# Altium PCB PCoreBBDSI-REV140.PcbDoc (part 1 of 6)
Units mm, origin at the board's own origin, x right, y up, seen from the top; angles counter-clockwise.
Board outline 100 x 72 mm, 6 copper layers (Top Layer, Int1 (GND), Int2 (Sign), Int3 (Sign), Int4 (GND), Bottom Layer), stack 1.551 mm thick; 358 components, 403 nets, 1535 pads, 844 vias.
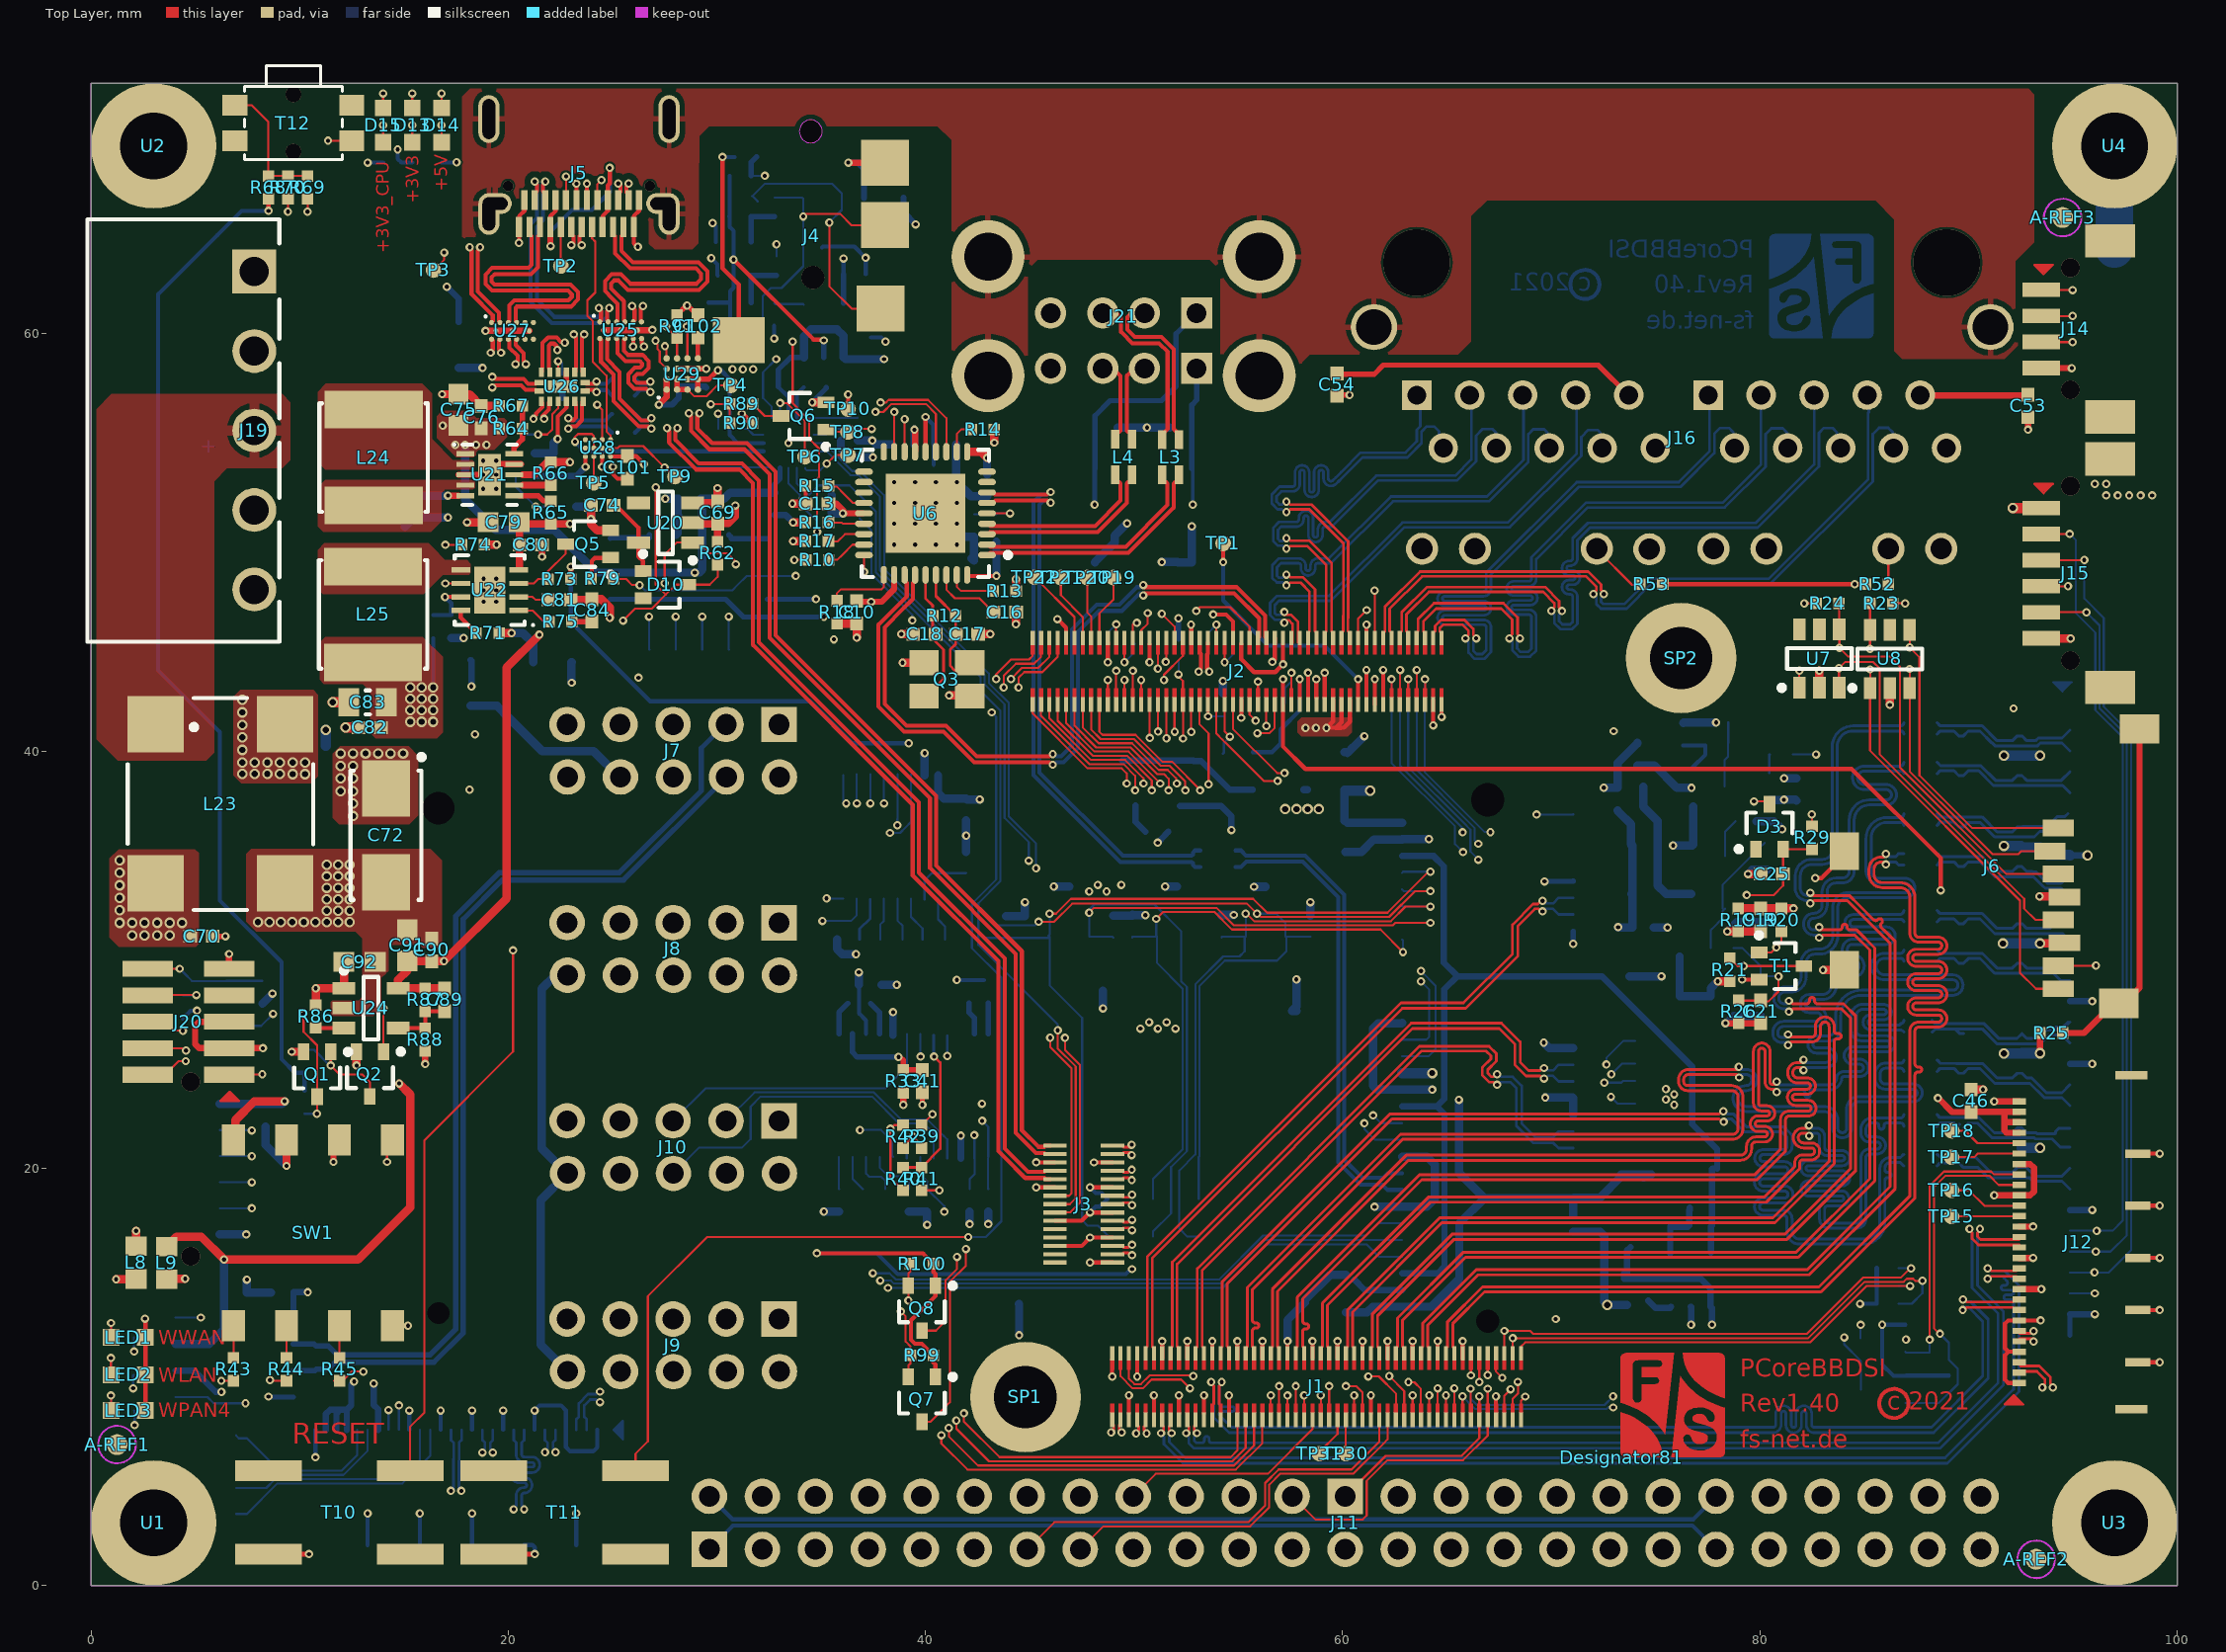
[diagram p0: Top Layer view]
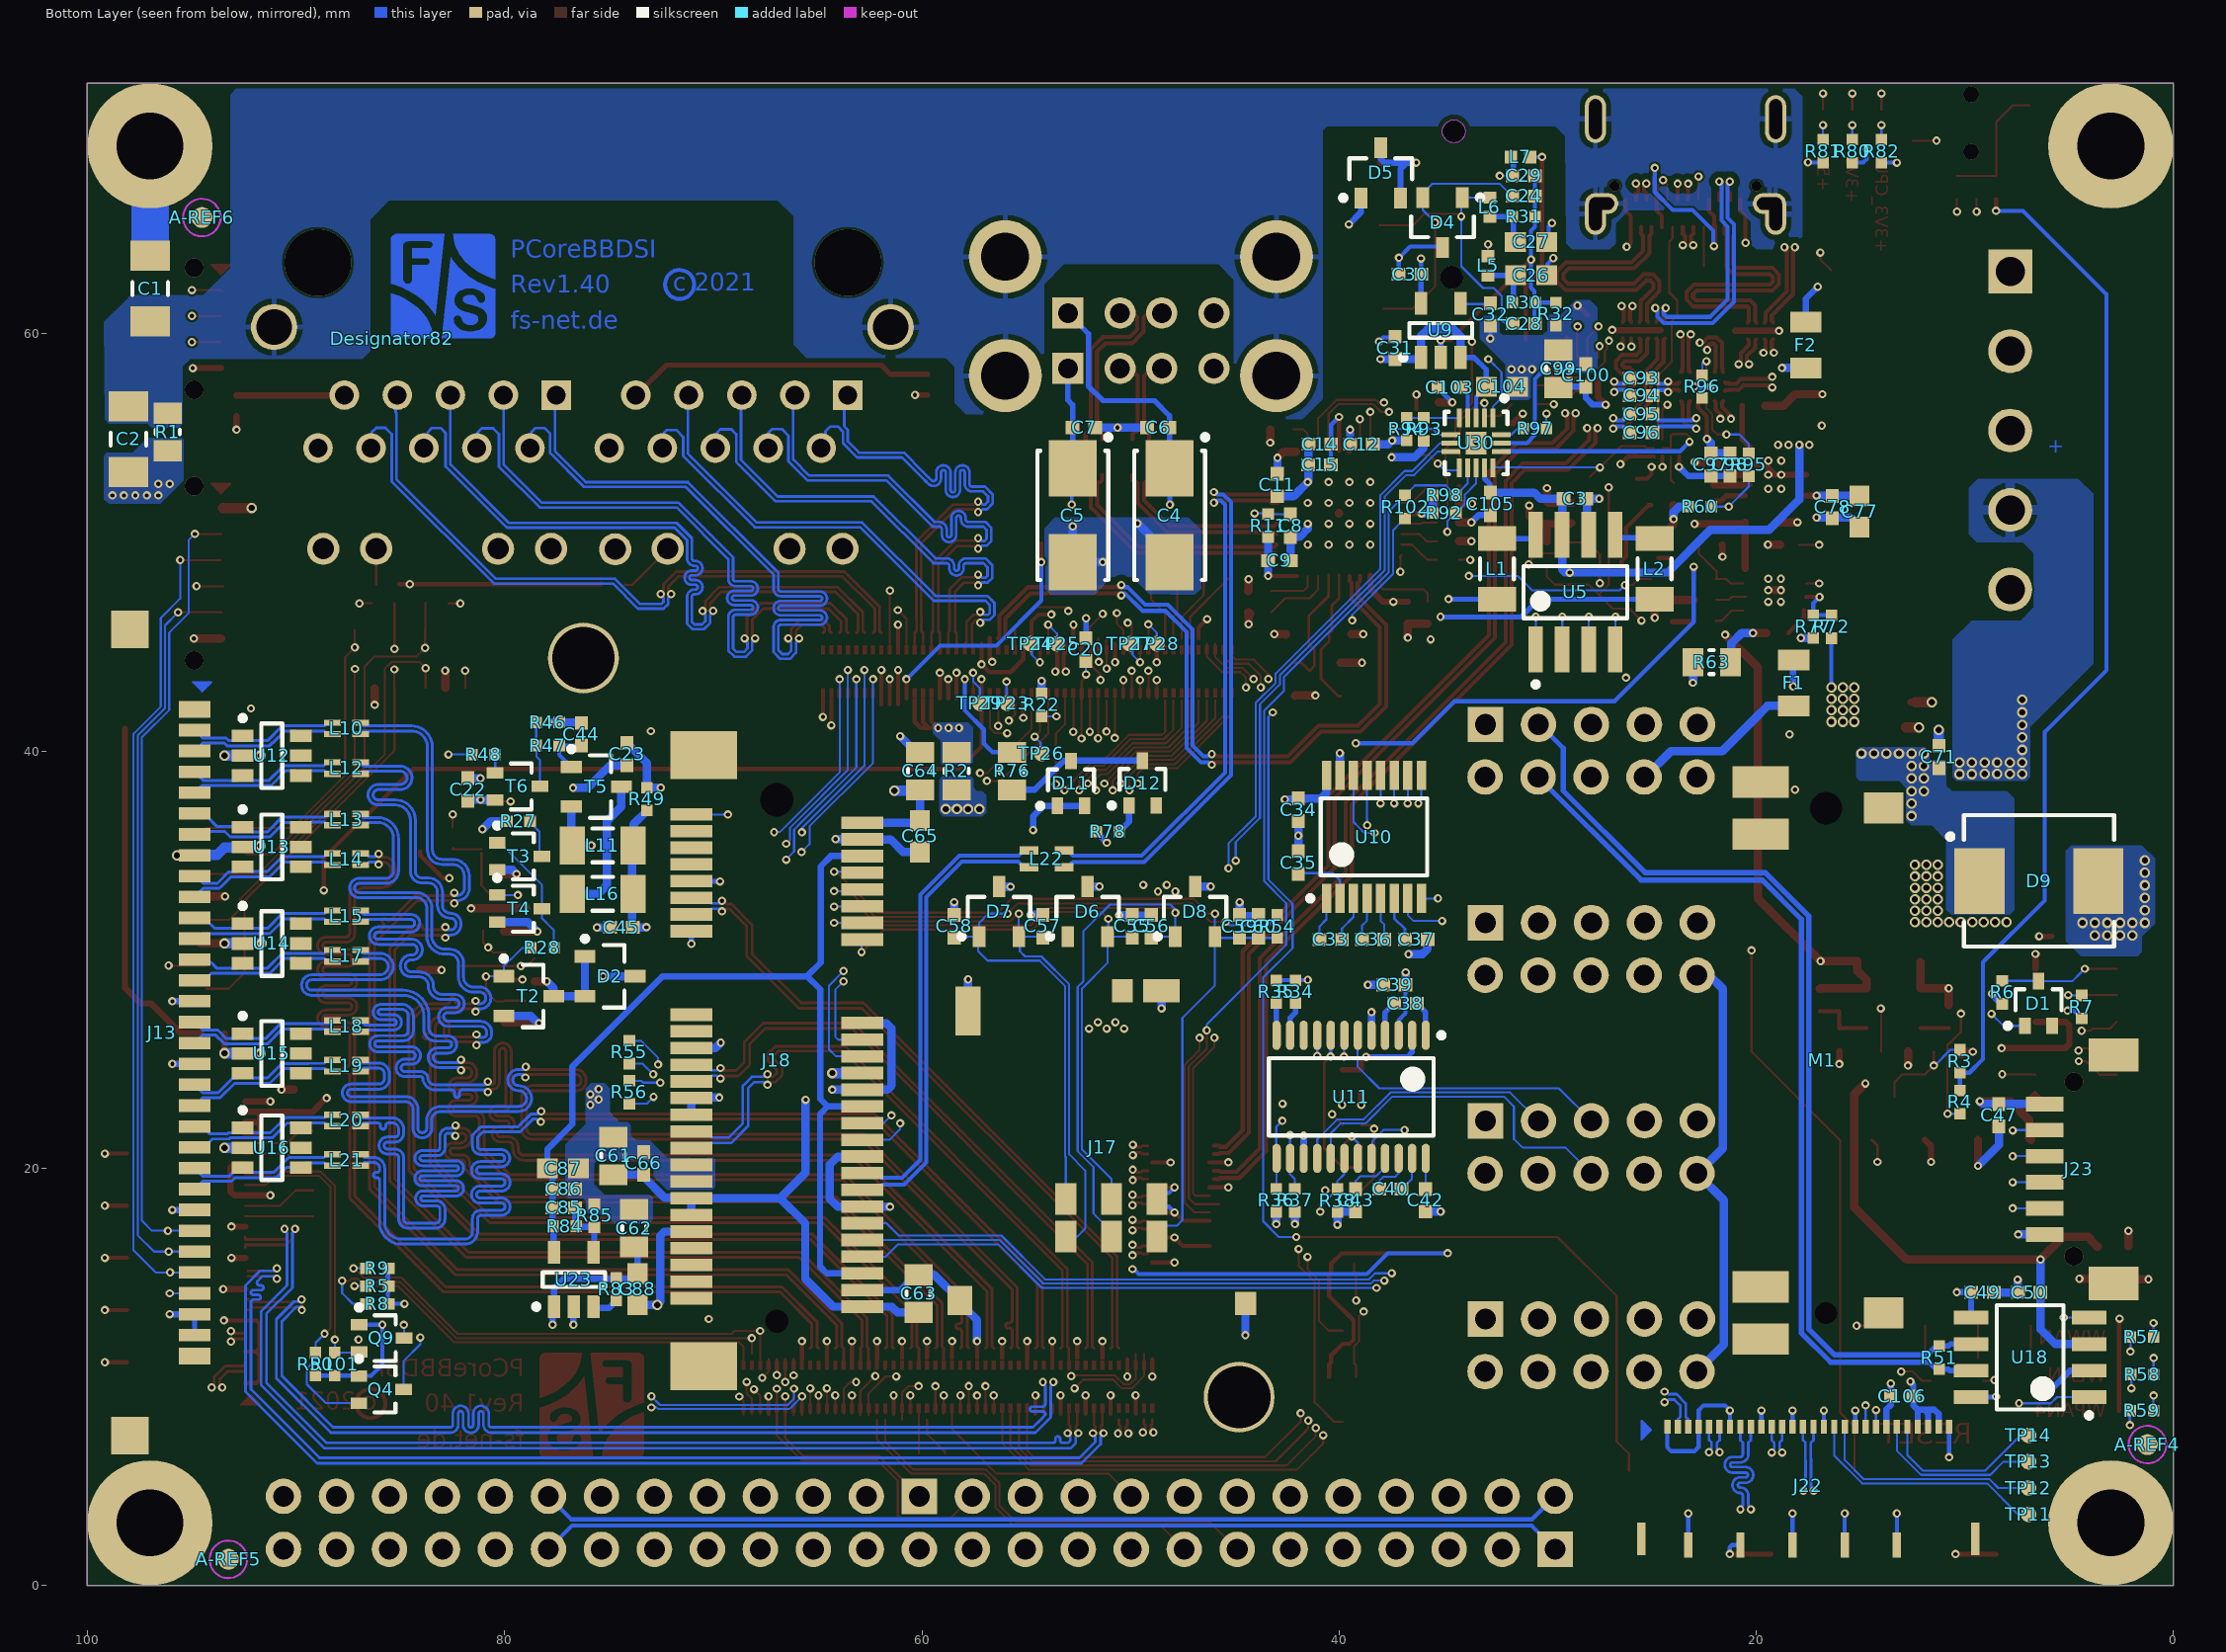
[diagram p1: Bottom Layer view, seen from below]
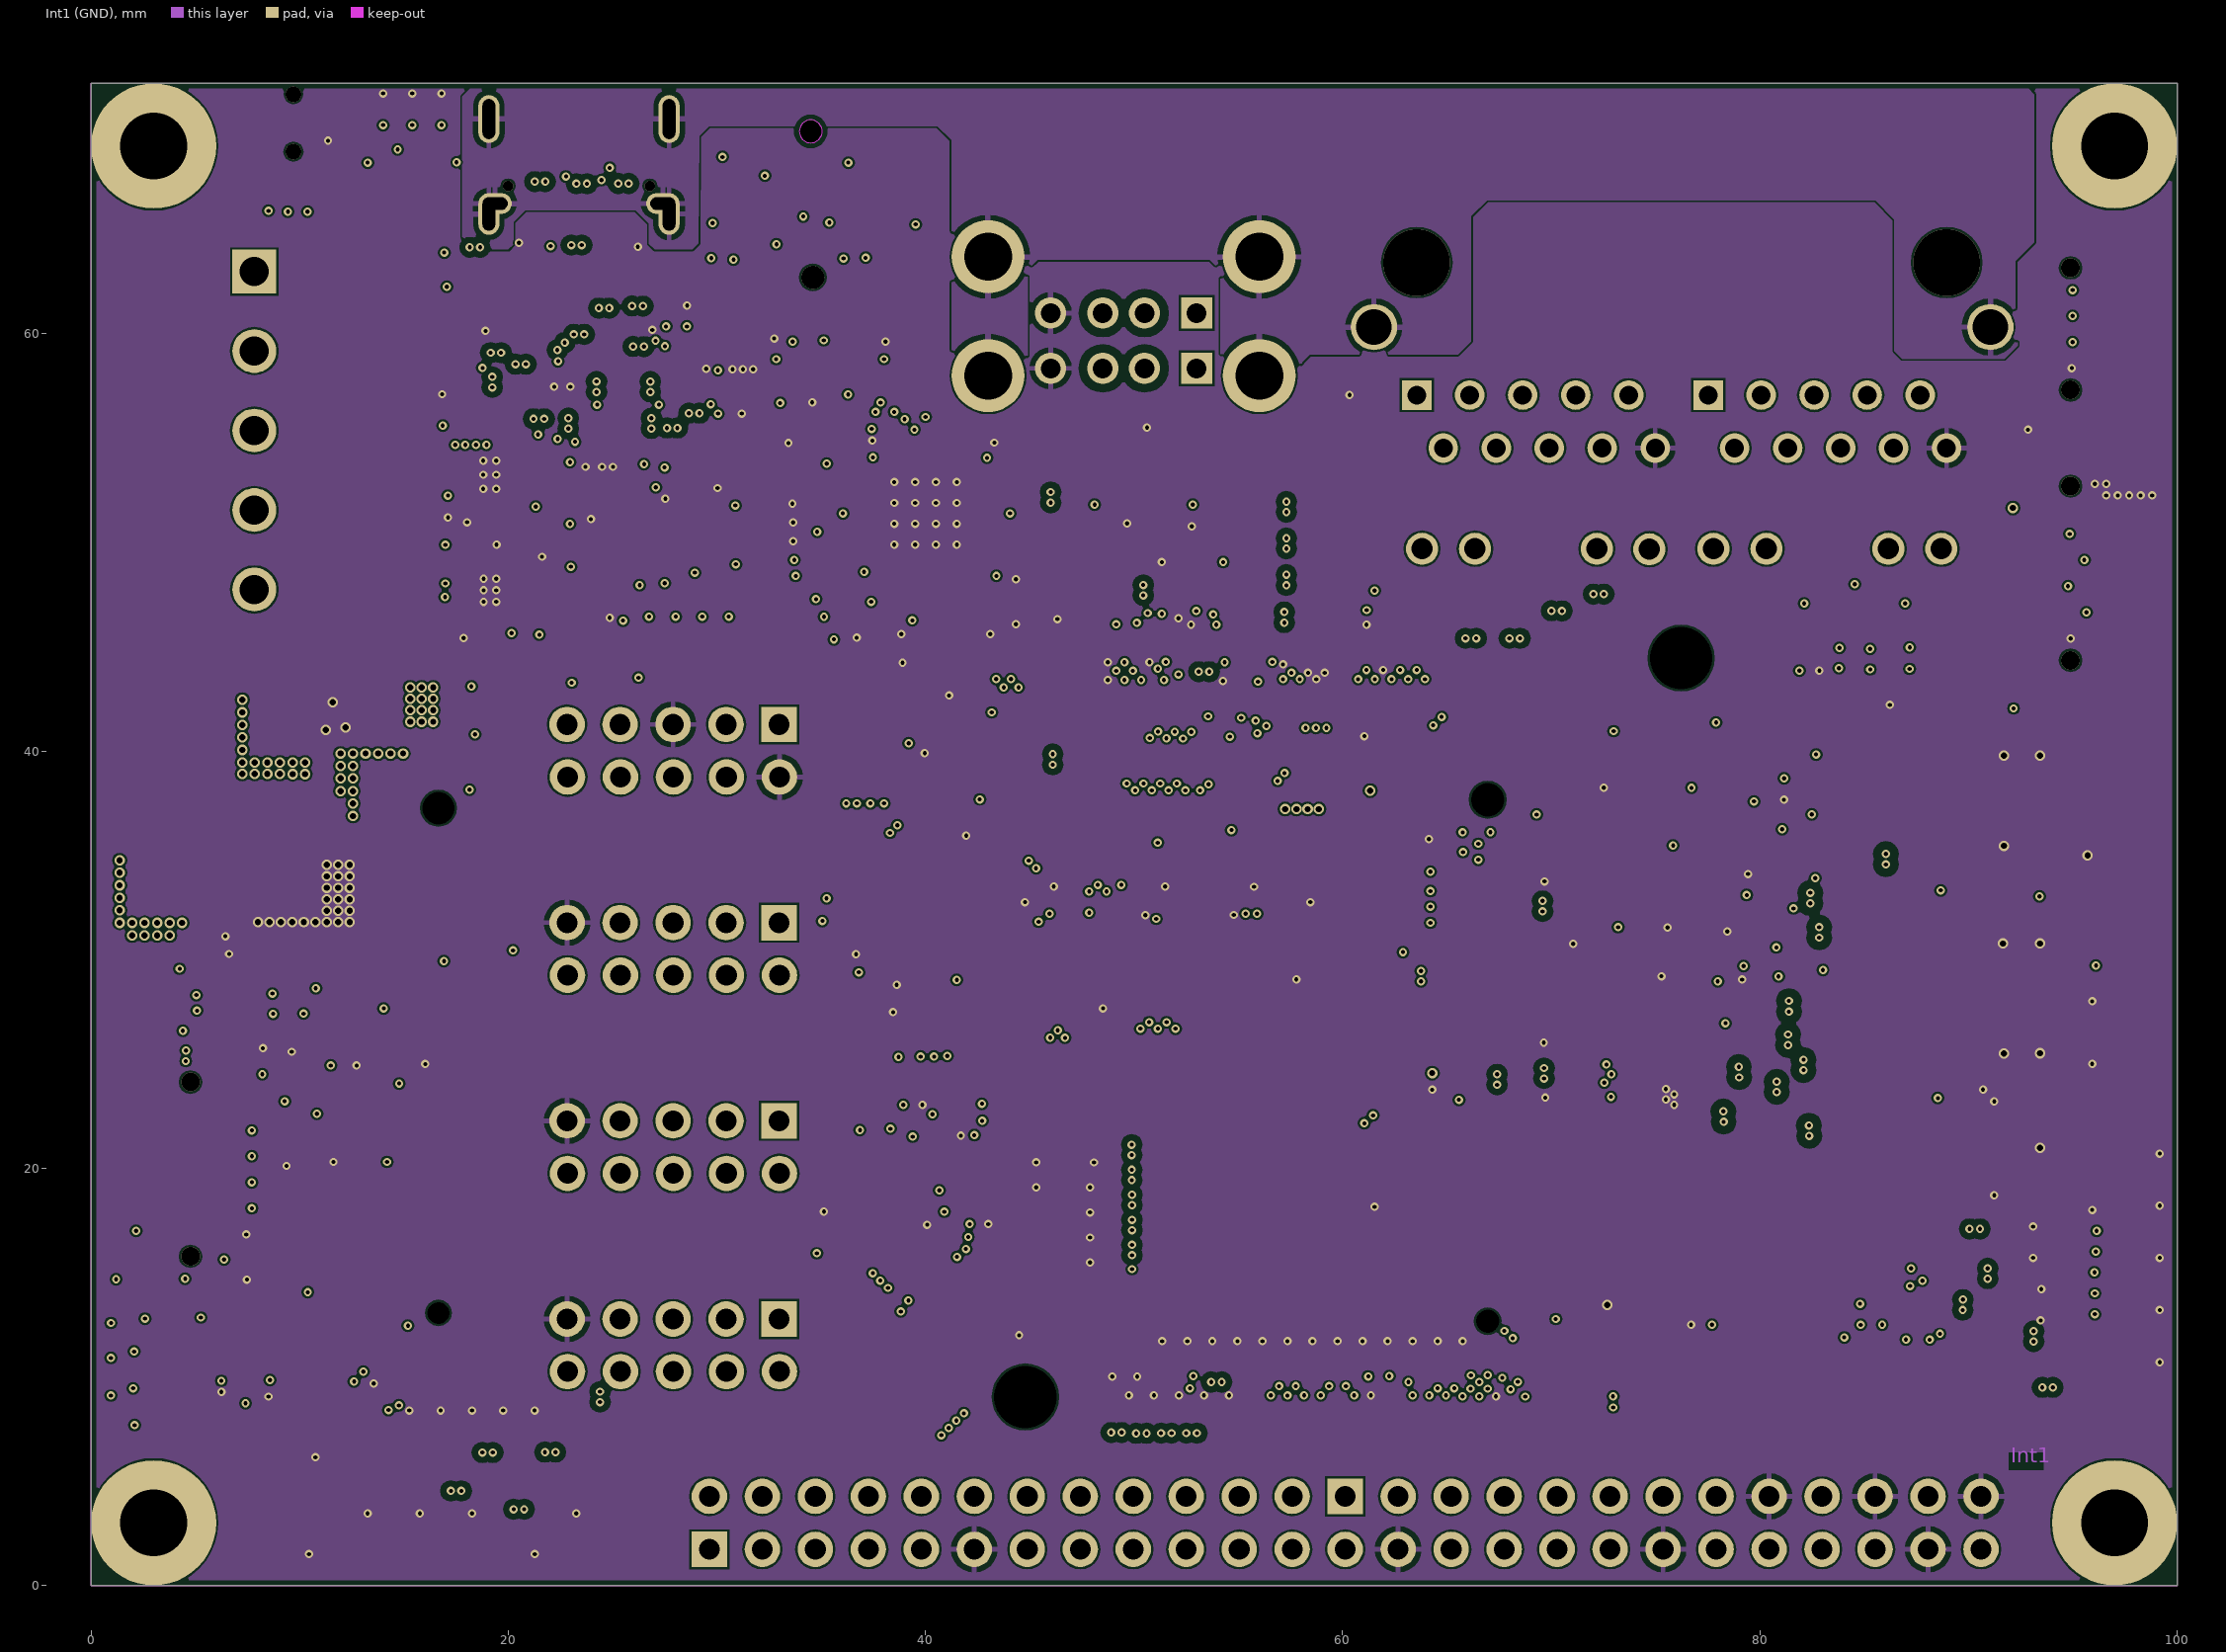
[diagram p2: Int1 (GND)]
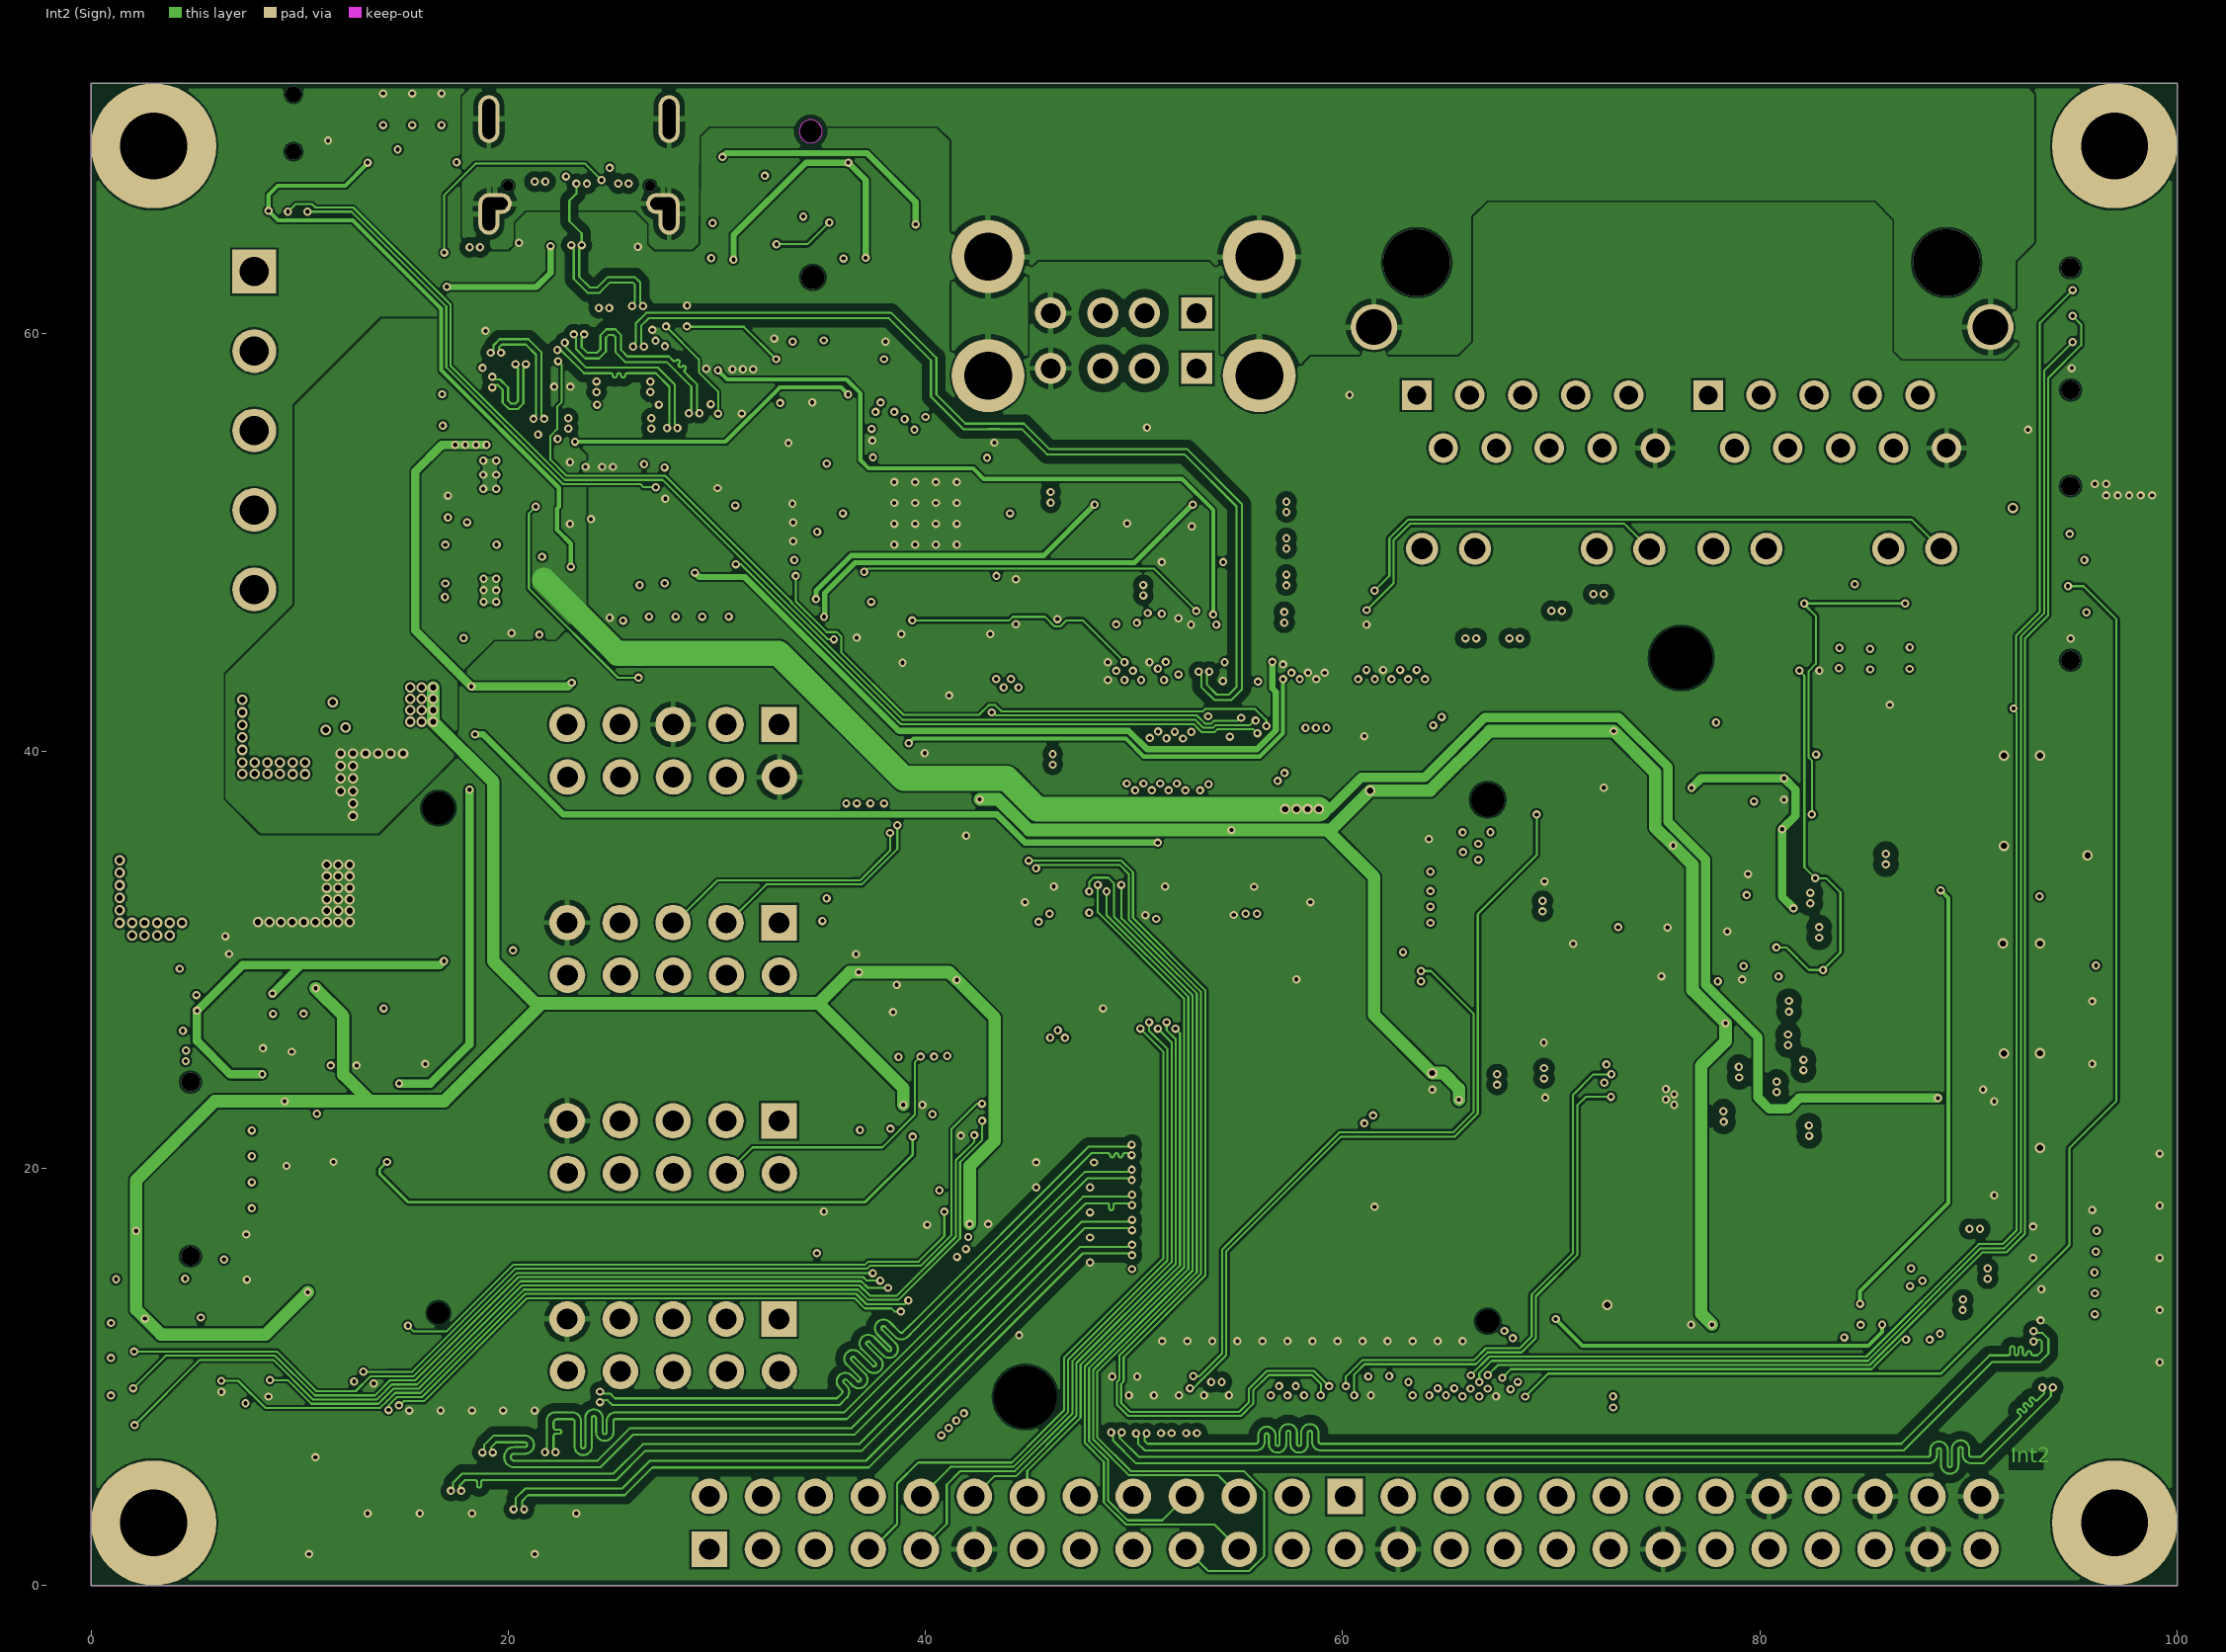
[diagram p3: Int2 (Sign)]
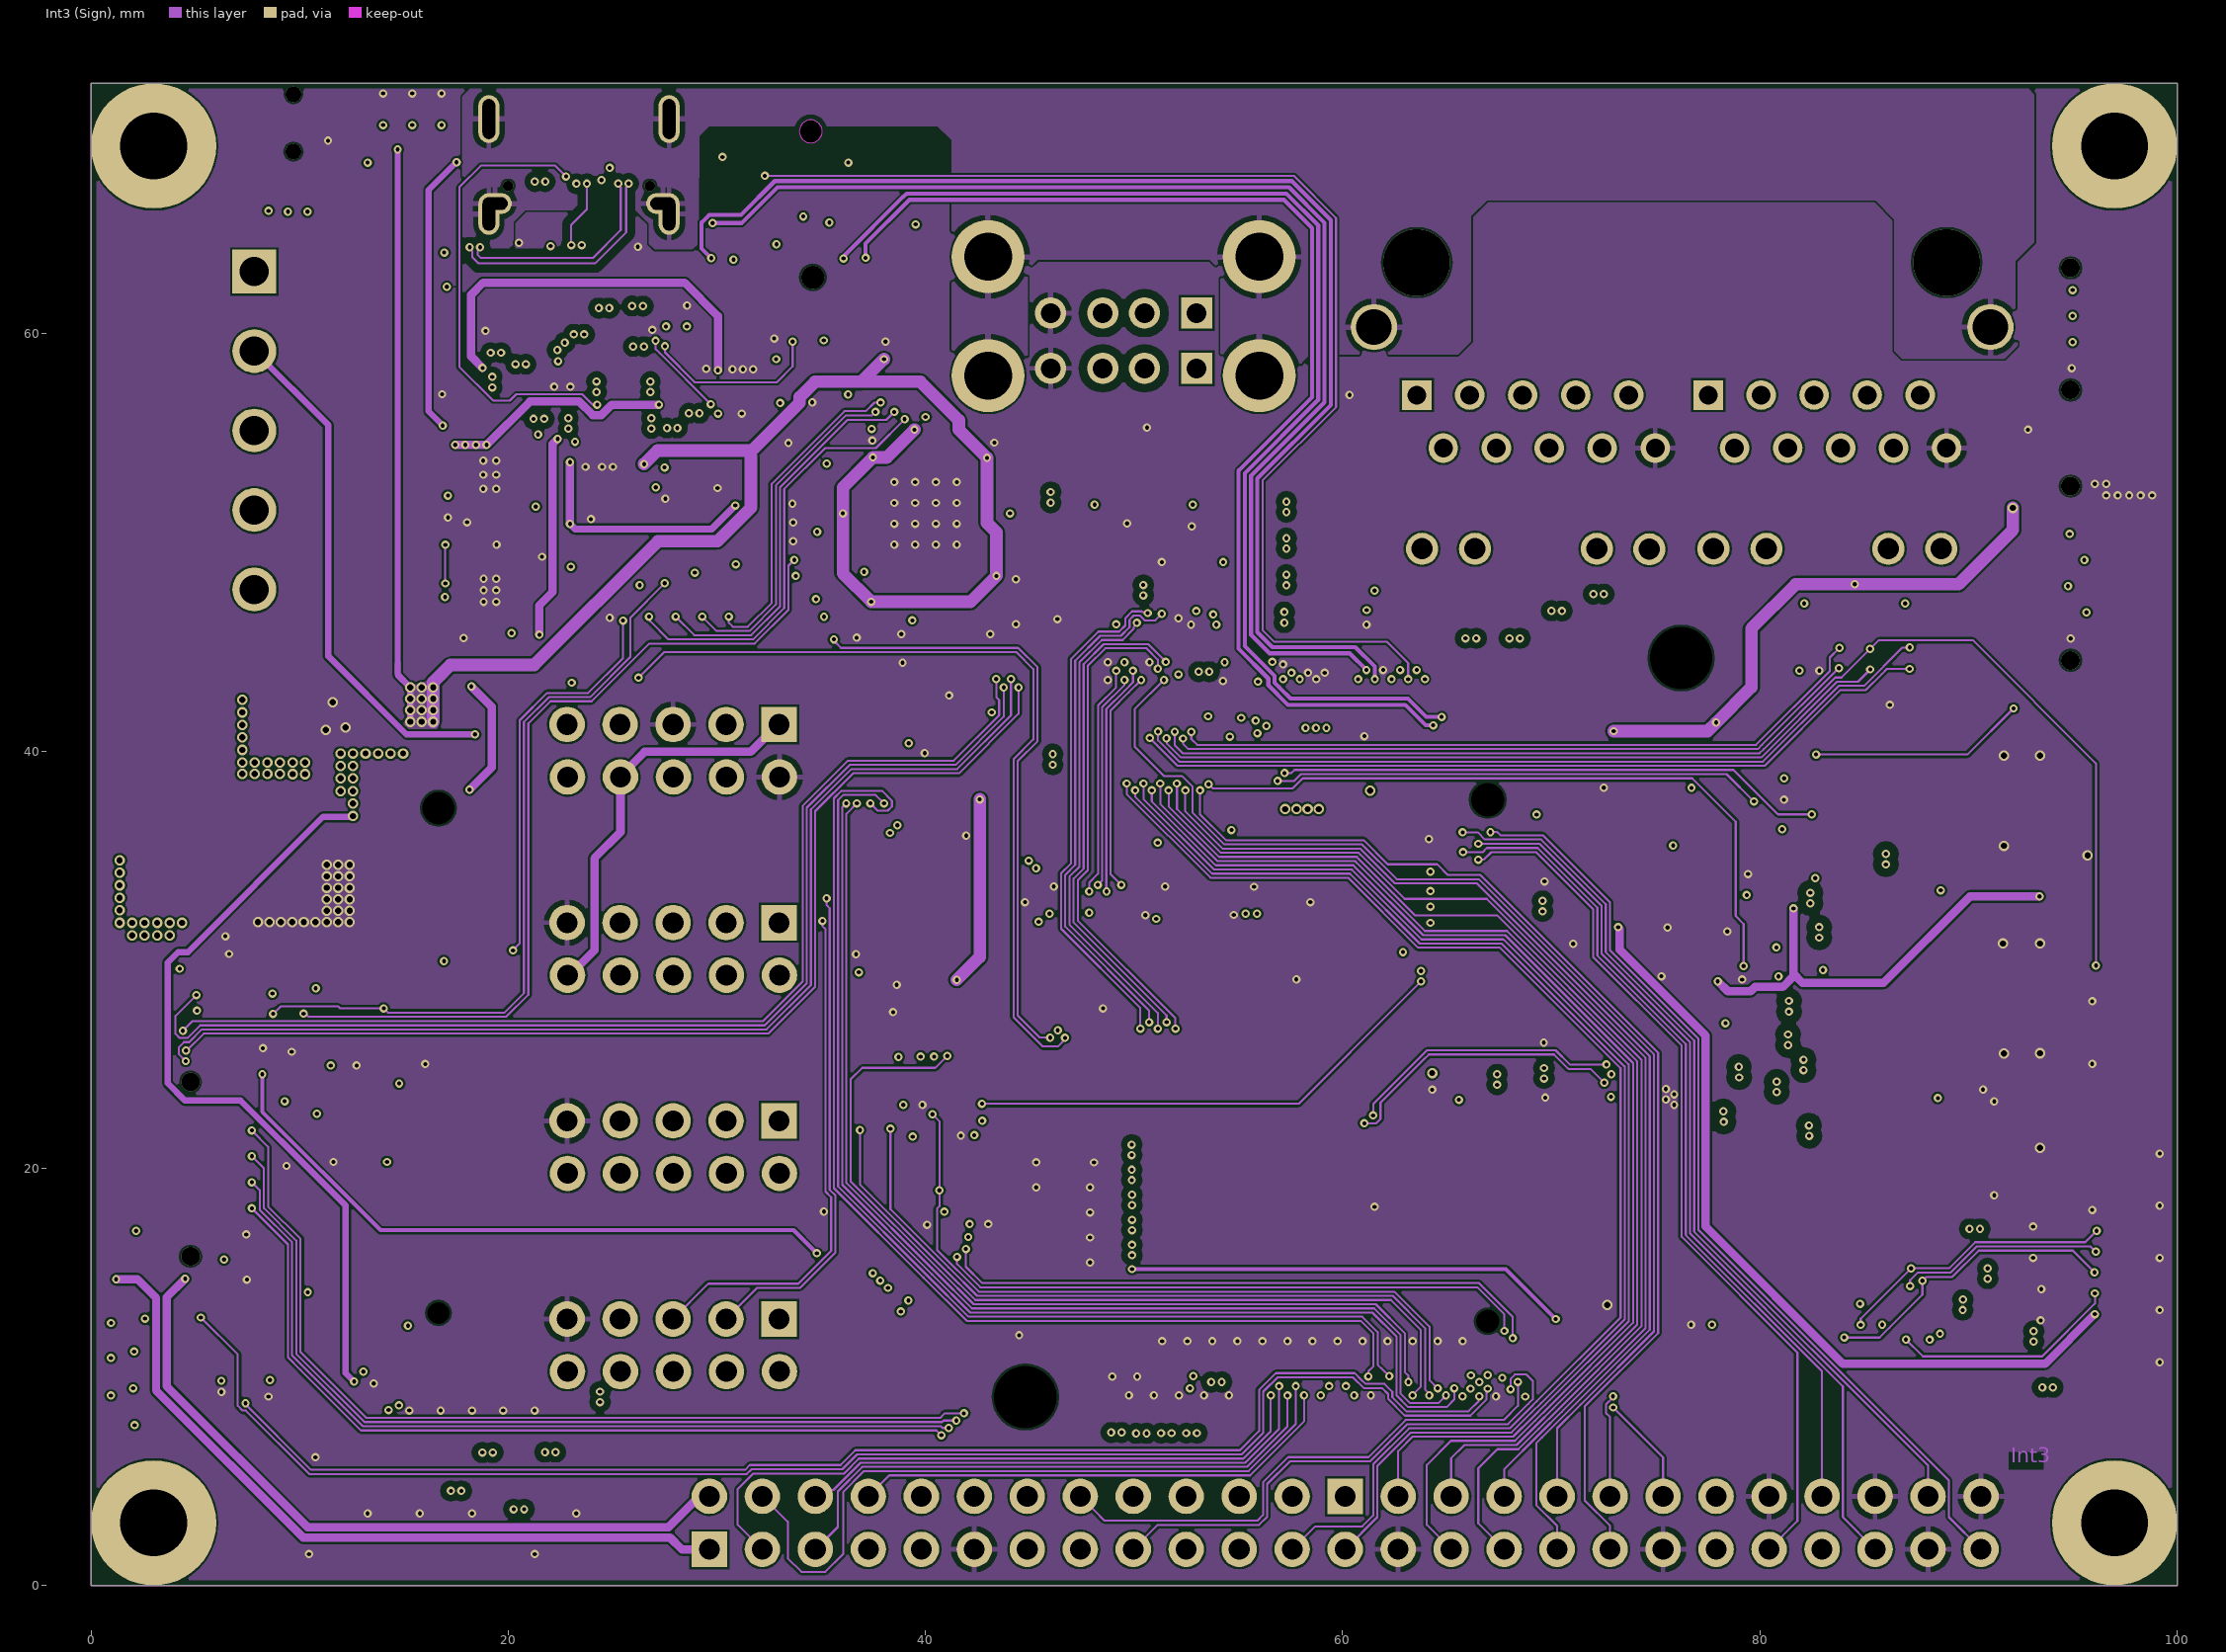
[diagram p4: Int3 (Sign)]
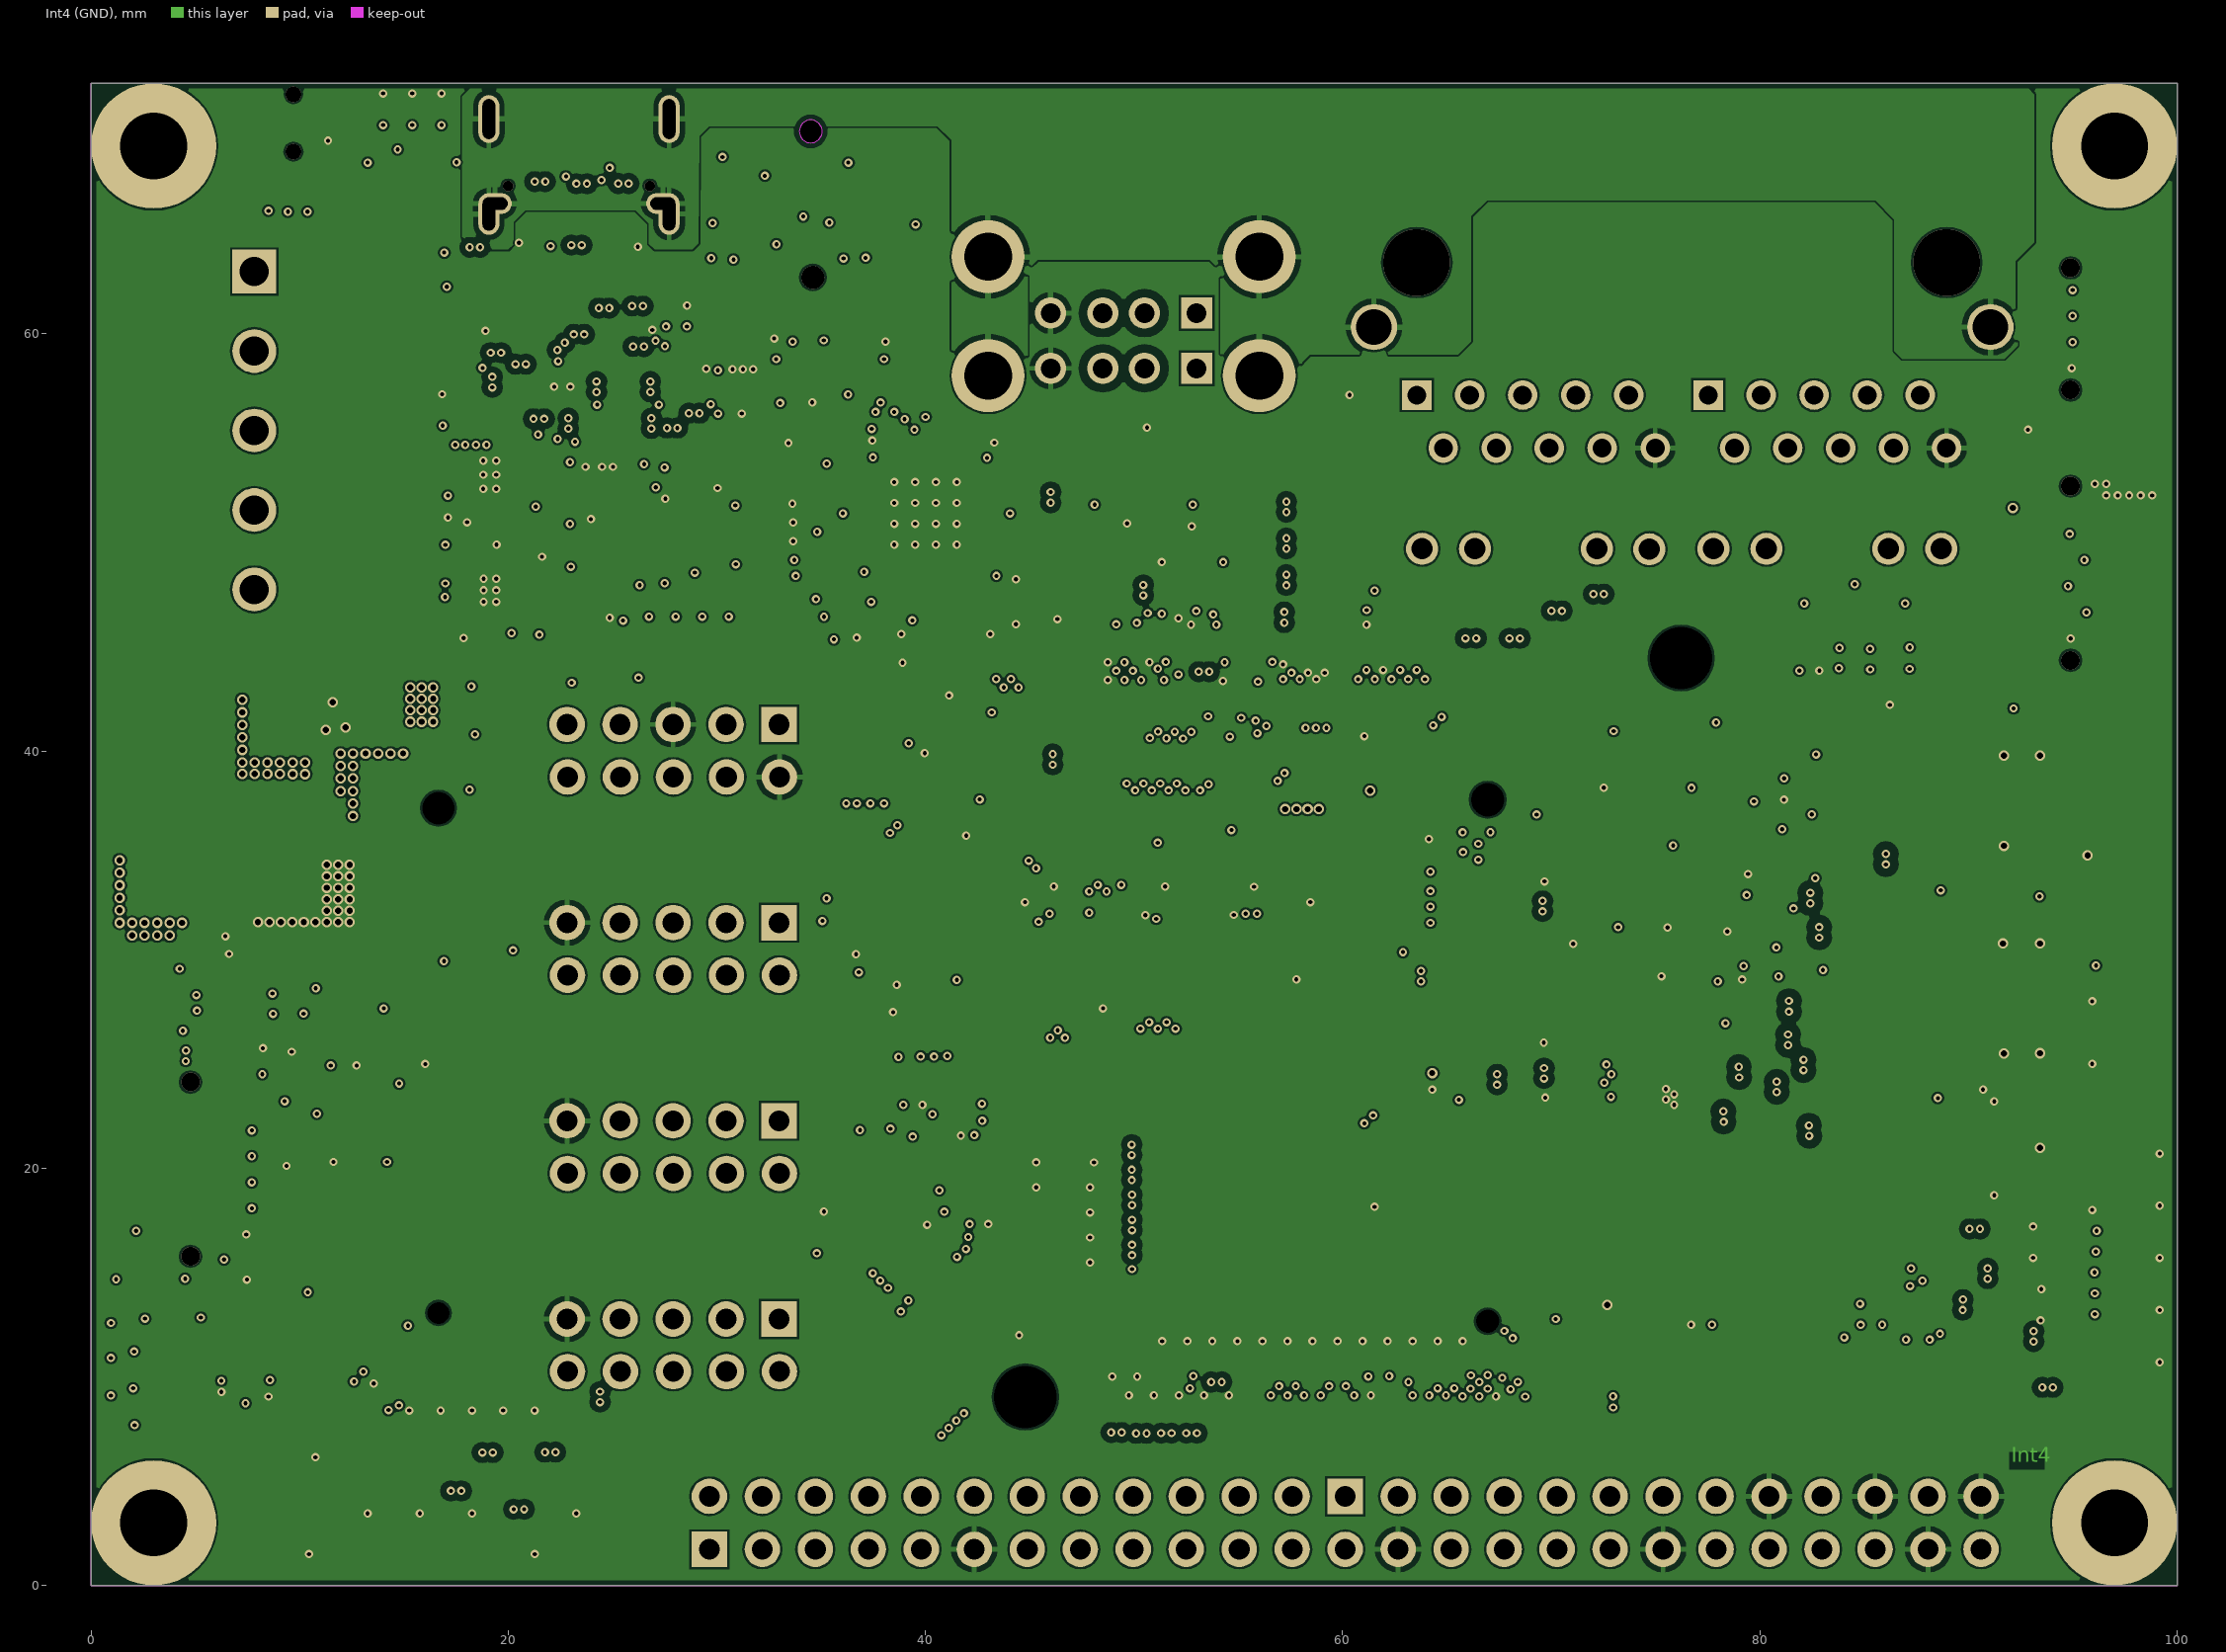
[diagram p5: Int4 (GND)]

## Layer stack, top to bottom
Top Solder: solder mask 0.0102, SM-001, Dk 3.5
Top Layer: signal copper 0.035
Dielectric 1: prepreg 0.0711, PP-006, Dk 4.1
Dielectric 2: prepreg 0.0711, PP-006, Dk 4.1
Int1 (GND): signal copper 0.035
Dielectric 3: core 0.4572, Core-035, Dk 4.7
Int2 (Sign): signal copper 0.035
Dielectric 4: prepreg 0.0711, PP-006, Dk 4.1
Dielectric 5: prepreg 0.0711, PP-006, Dk 4.1
Int3 (Sign): signal copper 0.035
Dielectric 6: core 0.4572, Core-035, Dk 4.7
Int4 (GND): signal copper 0.035
Dielectric 7: prepreg 0.0711, PP-006, Dk 4.1
Dielectric 8: prepreg 0.0711, PP-006, Dk 4.1
Bottom Layer: signal copper 0.035
Bottom Solder: solder mask 0.0102, SM-001, Dk 3.5

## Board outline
0,72 0,0 100,0 100,72
cut-out: 34.5,69.15 ccw(c34.5,69.7) 35.05,69.7 ccw(c34.5,69.7) 34.5,70.25 ccw(c34.5,69.7) 33.95,69.7 ccw(c34.5,69.7)

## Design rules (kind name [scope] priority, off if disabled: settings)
BoardOutlineClearance mdCopperDimension [All] p1: gap=0.254 ignorepadtopadclearanceinfootprint=FALSE except(0: Arc-SplitContinuation Track-SplitContinuation SMDPad-SplitContinuation THPad-SplitContinuation Via-SplitContinuation Fill-SplitContinuation Poly-SplitContinuation Region-SplitContinuation Text-SplitContinuation)
Clearance Clearance_ETH [InDifferentialPairClass('ETHERNET') and not InAnyComponent vs InNet('GND')] p1: gap=0.4 ignorepadtopadclearanceinfootprint=FALSE except(0.2: SMDPad-SMDPad SMDPad-THPad SMDPad-Via SMDPad-Fill SMDPad-Poly SMDPad-Region SMDPad-Text SMDPad-Hole Via-Via Via-Fill Via-Poly Via-Region Via-Text Via-Hole)
Clearance Clearance_USB [InDifferentialPairClass('USB') vs (InNet('GND') or InNet('GND_SHIELD')) and not InAnyComponent] p2: gap=0.4 ignorepadtopadclearanceinfootprint=FALSE except(0.2: SMDPad-SMDPad SMDPad-THPad SMDPad-Via SMDPad-Fill SMDPad-Poly SMDPad-Region SMDPad-Text SMDPad-Hole Via-Via Via-Fill Via-Poly Via-Region Via-Text Via-Hole)
Clearance Clearance_DSI [(InDifferentialPairClass('MIPI-DSI') or InDifferentialPairClass('MIPI-DSI_A'))and not InAnyComponent vs InNet('GND')] p3: gap=0.4 ignorepadtopadclearanceinfootprint=FALSE except(0.2: SMDPad-SMDPad SMDPad-THPad SMDPad-Via SMDPad-Fill SMDPad-Poly SMDPad-Region SMDPad-Text SMDPad-Hole)
Clearance Clearance_CSI [(InDifferentialPairClass('MIPI-CSI_A') or InDifferentialPairClass('MIPI-CSI_B')) and not InAnyComponent vs InNet('GND')] p4: gap=0.4 ignorepadtopadclearanceinfootprint=FALSE except(0.2: SMDPad-SMDPad SMDPad-THPad SMDPad-Via SMDPad-Fill SMDPad-Poly SMDPad-Region SMDPad-Text SMDPad-Hole Via-Via Via-Fill Via-Poly Via-Region Via-Text Via-Hole)
Clearance Clearance_MPCIE [InDifferentialPairClass('mPCIe') and not InAnyComponent vs InNet('GND')] p5: gap=0.4 ignorepadtopadclearanceinfootprint=FALSE except(0.2: SMDPad-SMDPad SMDPad-THPad SMDPad-Via SMDPad-Fill SMDPad-Poly SMDPad-Region SMDPad-Text SMDPad-Hole Via-Via Via-Fill Via-Poly Via-Region Via-Text Via-Hole)
Clearance [All] p6: gap=0.1 ignorepadtopadclearanceinfootprint=FALSE
DiffPairsRouting DiffPairsRouting_MIPI-CSIA [InDifferentialPairClass('MIPI-CSI_A')] p1: maxlimit=0.254 minlimit=0.134 mostfreqgap=0.217 toplayer_maxgap=0.134 toplayer_prefgap=0.134 toplayer_minwidth=0.127 toplayer_maxwidth=0.127 toplayer_prefwidth=0.127 midlayer2_mingap=0.217 midlayer2_maxgap=0.217 midlayer2_minwidth=0.1 midlayer2_maxwidth=0.1 midlayer2_prefwidth=0.1 midlayer13_mingap=0.217 midlayer13_maxgap=0.217 midlayer13_minwidth=0.1 midlayer13_maxwidth=0.1 midlayer13_prefwidth=0.1 bottomlayer_maxgap=0.134 bottomlayer_prefgap=0.134 bottomlayer_minwidth=0.127 bottomlayer_maxwidth=0.127 bottomlayer_prefwidth=0.127 impedanceprofiledriven=TRUE impedanceprofileid={61890842-8ADA-4508-8F82-990CEACFB491} impedanceprofilevalue=100.000000 maxuncoupledlength=12.7
DiffPairsRouting DiffPairsRouting_MIPI-CSIB [InDifferentialPairClass('MIPI-CSI_B')] p2: maxlimit=0.254 minlimit=0.134 mostfreqgap=0.217 toplayer_maxgap=0.134 toplayer_prefgap=0.134 toplayer_minwidth=0.127 toplayer_maxwidth=0.127 toplayer_prefwidth=0.127 midlayer2_mingap=0.217 midlayer2_maxgap=0.217 midlayer2_minwidth=0.1 midlayer2_maxwidth=0.1 midlayer2_prefwidth=0.1 midlayer13_mingap=0.217 midlayer13_maxgap=0.217 midlayer13_minwidth=0.1 midlayer13_maxwidth=0.1 midlayer13_prefwidth=0.1 bottomlayer_maxgap=0.134 bottomlayer_prefgap=0.134 bottomlayer_minwidth=0.127 bottomlayer_maxwidth=0.127 bottomlayer_prefwidth=0.127 impedanceprofiledriven=TRUE impedanceprofileid={61890842-8ADA-4508-8F82-990CEACFB491} impedanceprofilevalue=100.000000 maxuncoupledlength=12.7
DiffPairsRouting DiffPairsRouting_mPCIe [InDifferentialPairClass('mPCIe')] p3: maxlimit=0.254 minlimit=0.101 mostfreqgap=0.254 toplayer_maxgap=0.101 toplayer_prefgap=0.101 toplayer_minwidth=0.127 toplayer_maxwidth=0.127 toplayer_prefwidth=0.127 bottomlayer_maxgap=0.101 bottomlayer_prefgap=0.101 bottomlayer_minwidth=0.127 bottomlayer_maxwidth=0.127 bottomlayer_prefwidth=0.127 impedanceprofiledriven=TRUE impedanceprofileid={8104632F-C234-49EF-8071-15C0523083AF} impedanceprofilevalue=100.000000 maxuncoupledlength=12.7
DiffPairsRouting DiffPairsRouting_USB [InDifferentialPairClass('USB')] p4: maxlimit=0.254 minlimit=0.1 mostfreqgap=0.162 toplayer_maxgap=0.1 toplayer_prefgap=0.1 toplayer_minwidth=0.193 toplayer_maxwidth=0.193 toplayer_prefwidth=0.193 midlayer2_mingap=0.162 midlayer2_maxgap=0.162 midlayer2_minwidth=0.1 midlayer2_maxwidth=0.1 midlayer2_prefwidth=0.1 midlayer13_mingap=0.162 midlayer13_maxgap=0.162 midlayer13_minwidth=0.1 midlayer13_maxwidth=0.1 midlayer13_prefwidth=0.1 bottomlayer_maxgap=0.1 bottomlayer_prefgap=0.1 bottomlayer_minwidth=0.193 bottomlayer_maxwidth=0.193 bottomlayer_prefwidth=0.193 impedanceprofiledriven=TRUE impedanceprofileid={9E9B064C-F429-49DC-B595-341FB236020C} impedanceprofilevalue=90.000000 maxuncoupledlength=12.7
DiffPairsRouting DiffPairsRouting_ETH [InDifferentialPairClass('ETHERNET')] p5: maxlimit=0.254 minlimit=0.101 mostfreqgap=0.254 toplayer_maxgap=0.101 toplayer_prefgap=0.101 toplayer_minwidth=0.127 toplayer_maxwidth=0.127 toplayer_prefwidth=0.127 bottomlayer_maxgap=0.101 bottomlayer_prefgap=0.101 bottomlayer_minwidth=0.127 bottomlayer_maxwidth=0.127 bottomlayer_prefwidth=0.127 impedanceprofiledriven=TRUE impedanceprofileid={021EC69B-A8CB-46D2-9CD8-883BDBF6D44B} impedanceprofilevalue=100.000000 maxuncoupledlength=12.7
DiffPairsRouting DiffPairsRouting_MIPI-DSI [InDifferentialPairClass('MIPI-DSI')] p6: maxlimit=0.254 minlimit=0.1 mostfreqgap=0.254 toplayer_maxgap=0.1 toplayer_prefgap=0.1 toplayer_minwidth=0.141 toplayer_maxwidth=0.141 toplayer_prefwidth=0.141 bottomlayer_maxgap=0.1 bottomlayer_prefgap=0.1 bottomlayer_minwidth=0.141 bottomlayer_maxwidth=0.141 bottomlayer_prefwidth=0.141 impedanceprofiledriven=TRUE impedanceprofileid={A166DE6F-DE0D-4349-AD25-390A66383BFA} impedanceprofilevalue=100.000000 maxuncoupledlength=10
DiffPairsRouting DiffPairsRouting_MIPI-DSI_A [InDifferentialPairClass('MIPI-DSI_A')] p7: maxlimit=0.254 minlimit=0.1 mostfreqgap=0.254 toplayer_maxgap=0.1 toplayer_prefgap=0.1 toplayer_minwidth=0.141 toplayer_maxwidth=0.141 toplayer_prefwidth=0.141 bottomlayer_maxgap=0.1 bottomlayer_prefgap=0.1 bottomlayer_minwidth=0.141 bottomlayer_maxwidth=0.141 bottomlayer_prefwidth=0.141 impedanceprofiledriven=TRUE impedanceprofileid={A166DE6F-DE0D-4349-AD25-390A66383BFA} impedanceprofilevalue=100.000000 maxuncoupledlength=10
HoleSize [All] p1: absolutevalues=TRUE maxlimit=2540 minlimit=0.2 maxpercent=80.000 minpercent=20.000
HoleToHoleClearance mdDrill [All] p1: gap=0.203 allowstackedmicrovias=TRUE
MatchedLengths MatchedLengths_MIPI_CSI_A [InDifferentialPairClass('MIPI-CSI_A')] p1: tolerance=0.1 checknetsindiffpair=TRUE checkdiffpairvsdiffpair=FALSE checkxsignals=FALSE checkothers=FALSE
MatchedLengths MatchedLengths_MIPI_CSI_A2 [InDifferentialPairClass('MIPI-CSI_A')] p2: tolerance=0.1 checknetsindiffpair=FALSE checkdiffpairvsdiffpair=TRUE checkxsignals=TRUE checkothers=TRUE
MatchedLengths MatchedLengths_MIPI_CSI_B [InDifferentialPairClass('MIPI-CSI_B')] p3: tolerance=0.1 checknetsindiffpair=FALSE checkdiffpairvsdiffpair=TRUE checkxsignals=TRUE checkothers=TRUE
MatchedLengths MatchedLengths_MIPI_CSI_B_1 [InDifferentialPairClass('MIPI-CSI_B')] p4: tolerance=0.1 checknetsindiffpair=FALSE checkdiffpairvsdiffpair=TRUE checkxsignals=TRUE checkothers=TRUE
MatchedLengths MatchedLengths_MIPI_DSI_A [InDifferentialPairClass('MIPI-DSI_A')] p5: tolerance=0.1 checknetsindiffpair=TRUE checkdiffpairvsdiffpair=FALSE checkxsignals=FALSE checkothers=FALSE
MatchedLengths MatchedLengths_MIPI_DSI_A_2 [InDifferentialPairClass('MIPI-DSI_A')] p6: tolerance=0.2 checknetsindiffpair=FALSE checkdiffpairvsdiffpair=TRUE checkxsignals=TRUE checkothers=TRUE
MinimumSolderMaskSliver [All] p1 off: minsoldermaskwidth=0.254
PasteMaskExpansion Expansion_SMDPaste_OFF [InPadClass('SMDPaste_OFF')] p1: expansion=0
PasteMaskExpansion mlMinCreamFrame [All] p2: expansion=0
PlaneConnect [All] p1: planeconnectstyle=Direct reliefexpansion=0.508 reliefentries=4 reliefconductorwidth=0.254 reliefairgap=0.254
PolygonConnect [All] p1: thpad.connectstyle=Relief thpad.reliefconductorwidth=0.254 thpad.reliefentries=4 thpad.polygonreliefangle="90 Angle" thpad.airgapwidth=0.254 smdpad.connectstyle=Direct smdpad.reliefconductorwidth=0.254 smdpad.reliefentries=4 smdpad.polygonreliefangle="90 Angle" smdpad.airgapwidth=0.254 via.connectstyle=Direct via.reliefconductorwidth=0.254 via.reliefentries=4 via.polygonreliefangle="90 Angle" via.airgapwidth=0.254
RoutingVias [All] p1: holewidth=0.2 width=0.4 viastyle="Through Hole" minholewidth=0.2 minwidth=0.4 maxholewidth=5 maxwidth=5
SolderMaskExpansion Expansion_SMDSolder_OFF [InPadClass('SMDSolder_OFF')] p1: expansion=0 istentingtop=FALSE
SolderMaskExpansion mlMinStopFrame [All] p2: expansion=0 istentingtop=FALSE
Width [All] p1: maxlimit=2.54 minlimit=0.1 preferedwidth=0.1
24 further rules are at their usual default settings.

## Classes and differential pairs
differential pair class MIPI-CSI_A: CSI_A_CLK CSI_A_DATA0 CSI_A_DATA1 CSI_A_DATA2 CSI_A_DATA3
differential pair class MIPI-DSI: LACLK LADATA0 LADATA1 LADATA2 LADATA3 LBCLK LBDATA0 LBDATA1 LBDATA2 LBDATA3
component class "05) USB3.0 Type-C": C93 C94 C95 C96 C97 C98 C99 C100 C101 C102 C103 C104 C105 F2 J5 Q6 R60 R89 R90 R91 R92 R93 R94 R95 R96 R97 R98 R102 U25 U26 U27 U28 U29 U30
differential pair class MIPI-CSI_B: CSI_B_CLK CSI_B_DATA0 CSI_B_DATA1 CSI_B_DATA2 CSI_B_DATA3
differential pair class USB: S_TX1 S_TX2 SS_RX1 SS_RX2 SS_TX1 SS_TX2 SSRX1 SSRX2 SSTX1 SSTX2 USB1_CN_D USB1_RX USB1_TX USB_HUB_A USB_HUB_B USB_OTG USB_OTG_D USBD USBDM1 USBDM2 USBDM3 USBDM4 USBHUB_C USBOTG
differential pair class mPCIe: MPCIE_CLK MPCIE_CRX MPCIE_CTX
differential pair class ETHERNET: ETH_A_D1 ETH_A_D2 ETH_A_D3 ETH_A_D4 ETH_B_D1 ETH_B_D2 ETH_B_D3 ETH_B_D4
differential pair class MIPI-DSI_A: DSI_A_CLK DSI_A_DATA0 DSI_A_DATA1 DSI_A_DATA2 DSI_A_DATA3 DSI_B_CLK DSI_B_DATA0 DSI_B_DATA1 DSI_B_DATA2 DSI_B_DATA3
component class "10) DCDC": C69 C70 C71 C72 C74 C75 C76 C77 C78 C79 C80 C81 C82 C83 C84 C85 C86 C87 C88 C89 C90 C91 C92 D9 D10 D11 D12 D13 D14 D15 J19 L23 L24 L25 Q5 R62 R63 R64 R65 R66 R67 R68 R69 R70 R71 R72 R73 R74 R75 R76 R77 R78 R79 R80 R81 R82 R83 R84 R85 R86 R87 R88 T10 T11 T12 U20 U21 U22 U23 U24
component class "09) mPCIe": C55 C56 C57 C58 C59 C60 C61 C62 C63 C64 C65 C66 D6 D7 D8 J17 J18 L22 LED1 LED2 LED3 M1 R54 R55 R56 R57 R58 R59
component class "08) Ethernet Can": C49 C50 C53 C54 J7 J16 R51 R52 R53 U18
component class "07) LCD CAM": C44 C45 C46 C106 J12 J13 J14 J15 J22 L10 L11 L12 L13 L14 L15 L16 L17 L18 L19 L20 L21 Q4 Q7 Q8 Q9 R46 R47 R48 R49 R50 R99 R100 R101 T5 T6 U12 U13 U14 U15 U16
component class "06) Serial GPIO": C33 C34 C35 C36 C37 C38 C39 C40 C41 C42 C43 C47 F1 J8 J9 J10 J11 J23 L8 L9 R33 R34 R35 R36 R37 R38 R39 R40 R41 R42 R43 R44 R45 SW1 U10 U11
component class "04) USB AUDIO SD": C19 C20 C21 C22 C23 C24 C25 C26 C27 C28 C29 C30 C31 C32 D2 D3 D4 D5 J4 J6 L5 L6 L7 R19 R20 R21 R22 R23 R24 R25 R26 R27 R28 R29 R30 R31 R32 T1 T2 T3 T4 U7 U8 U9
component class "03) USB-HUB": C3 C4 C5 C6 C7 C8 C9 C10 C11 C12 C13 C14 C15 C16 C17 C18 J21 L1 L2 L3 L4 Q3 R10 R11 R12 R13 R14 R15 R16 R17 R18 U5 U6
component class "02) PicoCore B2B": D1 J1 J2 J3 J20 Q1 Q2 R2 R3 R4 R5 R6 R7 R8 R9 SP1 SP2
component class "01) Title Page": A-REF1 A-REF2 A-REF3 A-REF4 A-REF5 A-REF6 C1 C2 LABEL1 PCB1 R1 U1 U2 U3 U4
polygon class PolygonThermal_ON_Width50000_Gap100000: Polygon_1_Net_GND
polygon class PolygonThermal_ON_Width39400_Gap100000: Polygon_1_Net_VIN Polygon_2_Net_+3V3 Polygon_2_Net_N$3
polygon class PolygonThermal_ON_Width78700_Gap100000: Polygon_6_Net_GND
polygon class PolygonThermal_OFF: Polygon_1_Net_+3V3 Polygon_1_Net_GNDIN Polygon_1_Net_N$3 Polygon_1_Net_N$36 Polygon_1_Net_N$65 Polygon_1_Net_N$90 Polygon_1_Net_POWERIN Polygon_2_Net_GNDIN Polygon_3_Net_GND Polygon_4_Net_GND
pad class SMDSolder_OFF: A-REF1-P$1 A-REF2-P$1 A-REF3-P$1 A-REF4-P$1 A-REF5-P$1 A-REF6-P$1
pad class SMDPaste_OFF: A-REF1-P$1 A-REF2-P$1 A-REF3-P$1 A-REF4-P$1 A-REF5-P$1 A-REF6-P$1 C1-1 C1-2 C2-1 C2-2 C3-1 C3-2 C4-1 C4-2 C5-1 C5-2 C6-1 C6-2 C7-1 C7-2 C8-1 C8-2 C9-1 C9-2 C10-1 C10-2 C11-1 C11-2 C12-1 C12-2 C13-1 C13-2 C15-1 C15-2 C16-1 C16-2 C18-1 C18-2 C19-1 C19-2 C25-1 C25-2 C27-1 C27-2 C29-1 C29-2 C30-1 C30-2 C31-1 C31-2 C32-1 C32-2 C33-1 C33-2 C34-1 C34-2 C35-1 C35-2 C36-1 C36-2 C37-1 C37-2 C40-1 C40-2 C41-1 C41-2 C42-1 C42-2 C43-1 C43-2 C44-1 C44-2 C45-1 C45-2 C46-1 C46-2 C49-1 C49-2 C53-1 C53-2 C56-1 C56-2 C57-1 C57-2 C58-1 C58-2 C59-1 C59-2 C60-1 C60-2 C61-1 C61-2 C63-1 C63-2 C64-1 C64-2 C66-1 C66-2 C70-1 C70-2 C71-1 C71-2 C72-1 C72-2 C74-1 C74-2 C75-1 C75-2 C76-1 C76-2 C77-1 C77-2 C78-1 C78-2 C79-1 C79-2 C80-1 C80-2 C81-1 C81-2 C82-1 C82-2 C85-1 C85-2 C97-1 C97-2 C101-1 C101-2 C102-1 C102-2 C104-1 C104-2 C114-1 C114-2 C116-1 C116-2 IC11-P$37 IC17-9 R2-1 R2-2 R3-1 R3-2 R4-1 R4-2 R5-1 R5-2 R8-1 R8-2 R9-1 R9-2 R11-1 R11-2 R12-1 R12-2 R13-1 R13-2 R14-1 R14-2 R15-1 R15-2 R16-1 R16-2 R17-1 R17-2 R18-1 R18-2 R20-1 R20-2 R21-1 R21-2 R24-1 R24-2 R25-1 R25-2 R26-1 R26-2 R28-1 R28-2 R32-1 R32-2 R33-1 R33-2 R34-1 R34-2 R35-1 R35-2 R36-1 R36-2 R41-1 R41-2 R42-1 R42-2 R43-1 R43-2 R44-1 R44-2 R45-1 R45-2 R47-1 R47-2 R48-1 R48-2 R49-1 R49-2 R50-1 R50-2 R51-1 R51-2 R52-1 R52-2 R53-1 R53-2 R54-1 R54-2 R55-1 R55-2 R56-1 R56-2 R57-1 R57-2 R58-1 R58-2 R62-1 R62-2 R63-1 R63-2 R64-1 R64-2 R65-1 R65-2 R66-1 R66-2 R67-1 R67-2 R69-1 R69-2 R70-1 R70-2 R72-1 R72-2 R75-1 R75-2 R76-1 R76-2 R77-1 R77-2 R78-1 R78-2 R79-1 R79-2 R80-1 R80-2 R81-1 R81-2 R86-1 R86-2 U$11-11
differential pair CSI_A_DATA3: +CSI_A_DATA3_P -CSI_A_DATA3_N
differential pair CSI_A_DATA2: +CSI_A_DATA2_P -CSI_A_DATA2_N
differential pair CSI_A_DATA1: +CSI_A_DATA1_P -CSI_A_DATA1_N
differential pair CSI_A_DATA0: +CSI_A_DATA0_P -CSI_A_DATA0_N
differential pair CSI_A_CLK: +CSI_A_CLK_P -CSI_A_CLK_N
differential pair CSI_B_DATA3: +CSI_B_DATA3_P -CSI_B_DATA3_N
differential pair CSI_B_DATA2: +CSI_B_DATA2_P -CSI_B_DATA2_N
differential pair USB_OTG_D: +USB_OTG_D_P -USB_OTG_D_N
differential pair CSI_B_DATA1: +CSI_B_DATA1_P -CSI_B_DATA1_N
differential pair CSI_B_DATA0: +CSI_B_DATA0_P -CSI_B_DATA0_N
differential pair CSI_B_CLK: +CSI_B_CLK_P -CSI_B_CLK_N
differential pair USB1_CN_D: +USB1_CN_D_P -USB1_CN_D_N
differential pair USB1_TX: +USB1_TX_P -USB1_TX_N
differential pair USB1_RX: +USB1_RX_P -USB1_RX_N
differential pair SSTX2: +SSTX2_P -SSTX2_N
differential pair SSTX1: +SSTX1_P -SSTX1_N
differential pair SSRX2: +SSRX2_P -SSRX2_N
differential pair SSRX1: +SSRX1_P -SSRX1_N
differential pair SS_TX2: +SS_TX2_P -SS_TX2_N
differential pair SS_TX1: +SS_TX1_P -SS_TX1_N
differential pair SS_RX2: +SS_RX2_P -SS_RX2_N
differential pair SS_RX1: +SS_RX1_P -SS_RX1_N
differential pair S_TX2: +S_TX2_P -S_TX2_N
differential pair S_TX1: +S_TX1_P -S_TX1_N
differential pair LBDATA3: +LBDATA3_P -LBDATA3_N
differential pair LBDATA2: +LBDATA2_P -LBDATA2_N
differential pair LBDATA1: +LBDATA1_P -LBDATA1_N
differential pair LBDATA0: +LBDATA0_P -LBDATA0_N
differential pair LBCLK: +LBCLK_P -LBCLK_N
differential pair LADATA3: +LADATA3_P -LADATA3_N
differential pair LADATA2: +LADATA2_P -LADATA2_N
differential pair LADATA1: +LADATA1_P -LADATA1_N
differential pair LADATA0: +LADATA0_P -LADATA0_N
differential pair LACLK: +LACLK_P -LACLK_N
differential pair USBD: +USBD_P -USBD_N
differential pair USBHUB_C: +USBHUB_C_P -USBHUB_C_N
differential pair USBDM4: +USBDM4_P -USBDM4_N
differential pair USBDM3: +USBDM3_P -USBDM3_N
differential pair USBDM2: +USBDM2_P -USBDM2_N
differential pair USBDM1: +USBDM1_P -USBDM1_N
differential pair USB_HUB_B: +USB_HUB_B_P -USB_HUB_B_N
differential pair USB_HUB_A: +USB_HUB_A_P -USB_HUB_A_N
differential pair MPCIE_CTX: +MPCIE_CTX_P -MPCIE_CTX_N
differential pair MPCIE_CRX: +MPCIE_CRX_P -MPCIE_CRX_N
differential pair MPCIE_CLK: +MPCIE_CLK_P -MPCIE_CLK_N
differential pair ETH_B_D4: +ETH_B_D4_P -ETH_B_D4_N
differential pair ETH_B_D3: +ETH_B_D3_P -ETH_B_D3_N
differential pair ETH_B_D2: +ETH_B_D2_P -ETH_B_D2_N
differential pair ETH_B_D1: +ETH_B_D1_P -ETH_B_D1_N
differential pair ETH_A_D4: +ETH_A_D4_P -ETH_A_D4_N
differential pair ETH_A_D3: +ETH_A_D3_P -ETH_A_D3_N
differential pair ETH_A_D2: +ETH_A_D2_P -ETH_A_D2_N
differential pair ETH_A_D1: +ETH_A_D1_P -ETH_A_D1_N
differential pair DSI_B_DATA3: +DSI_B_DATA3_P -DSI_B_DATA3_N
differential pair DSI_B_DATA2: +DSI_B_DATA2_P -DSI_B_DATA2_N
differential pair DSI_B_DATA1: +DSI_B_DATA1_P -DSI_B_DATA1_N
differential pair DSI_B_DATA0: +DSI_B_DATA0_P -DSI_B_DATA0_N
differential pair DSI_B_CLK: +DSI_B_CLK_P -DSI_B_CLK_N
differential pair DSI_A_DATA3: +DSI_A_DATA3_P -DSI_A_DATA3_N
differential pair DSI_A_DATA2: +DSI_A_DATA2_P -DSI_A_DATA2_N
differential pair DSI_A_DATA1: +DSI_A_DATA1_P -DSI_A_DATA1_N
differential pair DSI_A_DATA0: +DSI_A_DATA0_P -DSI_A_DATA0_N
differential pair DSI_A_CLK: +DSI_A_CLK_P -DSI_A_CLK_N

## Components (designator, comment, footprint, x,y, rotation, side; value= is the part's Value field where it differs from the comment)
A-REF1 "REF" FIDUCIAL 1.25,6.75 r0 top
A-REF2 "REF" FIDUCIAL 93.24,1.25 r0 top
A-REF3 "REF" FIDUCIAL 94.51,65.57 r0 top
A-REF4 "REF" FIDUCIAL 1.25,6.75 r180 bottom
A-REF5 "REF" FIDUCIAL 93.24,1.25 r180 bottom
A-REF6 "REF" FIDUCIAL 94.51,65.57 r180 bottom
C1 "1nF" C1206 96.99,62.16 r90 bottom
C2 "1nF" C1206 98.03,54.95 r270 bottom
C3 "100nF" C0402 28.69,52.09 r0 bottom
C4 "220uF" C_2312 48.12,51.29 r270 bottom
C5 "220uF" C_2312 52.764,51.29 r270 bottom
C6 "100nF" C0402 48.67,55.5 r180 bottom
C7 "100nF" C0402 52.23,55.5 r0 bottom
C8 "100nF" C0402 42.33,50.8 r270 bottom
C9 "100nF" C0402 42.86,49.12 r0 bottom
C10 "100nF" C0402 36.7,46.65 r90 top
C11 "100nF" C0402 42.96,52.75 r90 bottom
C12 "100nF" C0402 38.93,54.7 r0 bottom
C13 "100nF" C0402 34.8,51.85 r0 top
C14 "100nF" C0402 40.92,54.7 r180 bottom
C15 "10uF" C0402 40.933,53.721 r180 bottom
C16 "10uF" C0402 43.8,46.65 r180 top
C17 "22pF" C0402 41.99,45.6 r180 top
C18 "22pF" C0402 39.95,45.6 r0 top
C19 "100nF" C0402 80.03,31.9 r90 top
C20 "22pF" C0402 52.13,44.86 r270 bottom
C21 "100nF" C0402 80.04,27.5 r270 top
C22 "100nF" C0402 81.76,38.15 r90 bottom
C23 "10uF" C0402 74.13,39.85 r270 bottom
C24 "220pF" C0402 31.15,66.6 r180 bottom
C25 "100nF" C0402 80.57,34.1 r0 top
C26 "22uF" C0603 30.79,62.8 r0 bottom
C27 "22uF" C0603 30.8,64.4 r0 bottom
C28 "220pF" C0402 31.14,60.48 r0 bottom
C29 "12pF" C0402 31.15,67.57 r0 bottom
C30 "10uF" C0402 36.6,62.85 r180 bottom
C31 "10uF" C0402 37.32,59.32 r270 bottom
C32 "10uF" C0402 32.75,60.92 r90 bottom
C33 "100nF" C0402 40.4,30.96 r0 bottom
C34 "100nF" C0402 41.95,37.18 r270 bottom
C35 "100nF" C0402 41.95,34.65 r90 bottom
C36 "100nF" C0402 38.37,30.97 r0 bottom
C37 "100nF" C0402 36.3,30.97 r180 bottom
C38 "100nF" C0402 36.82,27.9 r180 bottom
C39 "100nF" C0402 37.35,28.79 r0 bottom
C40 "100nF" C0402 37.54,19 r180 bottom
C41 "100nF" C0402 39.85,24.17 r270 top
C42 "100nF" C0402 35.86,18.46 r270 bottom
C43 "100nF" C0402 39.2,18.46 r270 bottom
C44 "100nF" C0402 76.32,40.8 r90 bottom
C45 "100nF" C0402 74.4,31.54 r180 bottom
C46 "100nF" C0402 90.12,23.23 r270 top
C47 "100nF" C0402 8.37,22.54 r90 bottom
C49 "100nF" C0402 9.16,14.04 r0 bottom
C50 "100nF" C0402 6.92,14.04 r0 bottom
C53 "100nF" C0402 92.85,56.54 r90 top
C54 "100nF" C0402 59.73,57.56 r90 top
C55 "47pF" C0402 49.92,31.6 r270 bottom
C56 "47pF" C0402 49,31.6 r270 bottom
C57 "47pF" C0402 54.2,31.6 r270 bottom
C58 "47pF" C0402 58.45,31.6 r270 bottom
C59 "47pF" C0402 44.77,31.59 r270 bottom
C60 "100nF" C0402 43.86,31.59 r270 bottom
C61 "47uF" C0805 74.8,20.59 r270 bottom
C62 "47uF" C0805 73.79,17.12 r270 bottom
C63 "47uF" C0805 60.16,13.99 r270 bottom
C64 "47uF" C0805 60.09,39.04 r270 bottom
C65 "10uF" C0603 60.09,35.91 r90 bottom
C66 "100nF" C0402 73.34,20.23 r270 bottom
C69 "100nF" C0402 30.04,51.43 r270 top
C70 "100nF" C0402 5.29,31.12 r180 top
C71 "100nF" C0402 11.25,39.71 r270 bottom
C72 "220uF" C_2312 14.14,35.96 r270 top
C74 "100nF" C0402 24.5,51.78 r0 top
C75 "10uF" C0603 17.614,56.35 r270 top
C76 "100nF" C0402 18.704,56 r270 top
C77 "10uF" C0603 15.05,51.48 r90 bottom
C78 "100nF" C0402 16.35,51.69 r90 bottom
C79 "10uF" C0603 19.78,50.96 r0 top
C80 "100nF" C0402 21.08,49.88 r180 top
C81 "100pF" C0402 22.45,47.24 r180 top
C82 "100nF" C0402 13.36,41.12 r0 top
C83 "0,22uF" C0805 13.26,42.33 r0 top
C84 "560pF" C0402 24.01,46.74 r270 top
C85 "560pF" C0402 77.17,18.1 r0 bottom
C86 "100nF" C0402 77.17,19 r0 bottom
C87 "10uF" C0603 77.2,19.99 r0 bottom
C88 "10uF" C0603 73.63,14.2 r90 bottom
C89 "560pF" C0402 16.95,28.07 r90 top
C90 "100nF" C0402 16.33,30.46 r270 top
C91 "10uF" C0603 15.16,30.68 r270 top
C92 "10uF" C0603 12.87,29.89 r180 top
C93 "100nF" C0402 25.52,57.864 r180 bottom
C94 "100nF" C0402 25.52,57.034 r180 bottom
C95 "100nF" C0402 25.52,56.145 r180 bottom
C96 "100nF" C0402 25.52,55.265 r180 bottom
C97 "100nF" C0402 22.17,53.72 r90 bottom
C98 "10uF" C0402 21.26,53.72 r90 bottom
C99 "47uF" C0805 29.49,58.32 r270 bottom
C100 "100nF" C0402 28.17,58 r270 bottom
C101 "100nF" C0402 25.71,53.59 r90 top
C102 "1nF" C0402 29.09,60.35 r90 top
C103 "2,2uF" C0402 34.7,57.43 r180 bottom
C104 "22uF" C0603 32.19,57.46 r0 bottom
C105 "100nF" C0402 32.75,51.84 r90 bottom
C106 "100nF" C0402 13.01,9.07 r180 bottom
D1 "BAT54CW" "SOT323 (SC70)" 6.47,27.9 r90 bottom
D2 "TVS Diode" SOT23-3 74.95,29.2 r180 bottom
D3 "BAT54CW" "SOT323 (SC70)" 80.46,36.37 r90 top
D4 "TVS Diode" SOT23-3 35.04,65.33 r270 bottom
D5 "TVS Diode" SOT23-3 38,67.71 r90 bottom
D6 "TVS Diode" SOT23-3 52.05,32.3 r90 bottom
D7 "TVS Diode" SOT23-3 56.3,32.3 r90 bottom
D8 "TVS Diode" SOT23-3 46.9,32.3 r90 bottom
D9 "SK56L" DO-214AB 6.45,33.77 r180 bottom
D10 "BAT54CW" "SOT323 (SC70)" 27.535,47.97 r0 top
D11 "BAT54CW" "SOT323 (SC70)" 52.85,38.44 r90 bottom
D12 "BAT54CW" "SOT323 (SC70)" 49.42,38.46 r90 bottom
D13 "Green" LED0603 15.4,70 r270 top locked
D14 "Green" LED0603 16.8,70 r270 top locked
D15 "Green" LED0603 14,70 r270 top locked
Designator81 "Comment" "F&S LOGO 5x5mm" 73.36,6.14 r0 top
Designator82 "Comment" "F&S LOGO 5x5mm" 85.406,59.78 r180 bottom
F1 "0805L100WR" FUSE0805 18.2,43.26 r270 bottom
F2 "0805L100WR" FUSE0805 17.63,59.46 r270 bottom
J1 "PicoCoreMX8MM_J1" DF40C-100DS-0.4V(51) 58.75,9.53 r180 top locked
J2 "PicoCoreMX8MM_J2" DF40C-100DS-0.4V(51) 54.94,43.82 r180 top locked
J3 "DF40C-30DP-0.4V(51)" DF40C-30DS-0.4V(51) 47.584,18.276 r0 top
J4 "SJ2-3574A-SMT-TR" SJ2-3574A-SMT-TR 34.5,65.1 r270 top locked
J5 "UC-3019-2GNB-RR" UC-3019-2GNB-RR 23.39,68.94 r180 top
J6 "µSD" MICROSD_PUSH-PULL 91.25,34.45 r270 top locked
J7 "2x5pol. RM2.54" COM-5X2 27.9,40 r180 top
J8 "2x5pol. RM2.54" COM-5X2 27.9,30.5 r180 top
J9 "2x5pol. RM2.54" COM-5X2 27.9,11.5 r180 top
J10 "2x5pol. RM2.54" COM-5X2 27.9,21 r180 top
J11 "PRPC025DAAN-RC" COM-25X2 60.12,3 r0 top locked
J12 "FH41-28S-0.5SH(05)" FH41-28S-0.5SH(05) 95.41,16.45 r90 top
J13 "1002MR-30GW-U" JAE-30POL. 96.91,26.5 r90 bottom
J14 "DF13-4P-1.25H(20)" DF13-4P-1.25H(20) 96.99,60.23 r270 top locked
J15 "DF13-6P-1.25H(20)" DF13-6P-1.25H(20) 96.99,48.52 r270 top locked
J16 "TRJG27440ADNL" TRJG27440ADNL 76.25,61.46 r180 top locked
J17 "SF56K006VBAR2000" SF56K006VBAR2000 51.38,21.06 r180 bottom
J18 "mPCIe" MM60-52B1-E1-R650 66.95,25.16 r270 bottom
J19 "MC 1,5/ 5-G-3,81" 691322310005 4.425,55.36 r270 top locked
J20 "" J-B2B-5X2-127MM-WR-PHD 4.67,27.02 r90 top
J21 "USB-Einbaukupplung zweifach liegend" LUMBERG-2410-03 49.5,60.84 r0 top locked
J22 "FH41-28S-0.5SH(05)" FH41-28S-0.5SH(05) 17.51,4.635 r180 bottom
J23 "DF13-6P-1.25H(20)" DF13-6P-1.25H(20) 2.67,19.95 r270 bottom
L1 "700R /90MHz" L1206 32.43,48.73 r90 bottom
L2 "700R /90MHz" L1206 24.88,48.73 r90 bottom
L3 "2x90R/100MHz" USBSHOCK4-0805-12 51.75,54.08 r90 top
L4 "2x90R/100MHz" USBSHOCK4-0805-12 49.5,54.09 r90 top
L5 "120R/100MHz" L0402 32.86,63.26 r90 bottom
L6 "120R/100MHz" L0402 32.77,66.07 r90 bottom
L7 "120R/100MHz" L0402 31.3,68.47 r180 bottom
L8 "120R/100MHz" L0603 2.165,15.47 r270 top
L9 "120R/100MHz" L0603 3.62,15.46 r90 top
L10 "2x90R" DLP11SN900HL2L 87.57,41.08 r0 bottom
L11 "700R /90MHz" L1206 75.3,35.47 r180 bottom
L12 "2x90R" DLP11SN900HL2L 87.57,39.18 r0 bottom
L13 "2x90R" DLP11SN900HL2L 87.57,36.71 r0 bottom
L14 "2x90R" DLP11SN900HL2L 87.57,34.81 r0 bottom
L15 "2x90R" DLP11SN900HL2L 87.57,32.08 r0 bottom
L16 "700R /90MHz" L1206 75.3,33.15 r180 bottom
L17 "2x90R" DLP11SN900HL2L 87.57,30.18 r0 bottom
L18 "2x90R" DLP11SN900HL2L 87.57,26.81 r0 bottom
L19 "2x90R" DLP11SN900HL2L 87.57,24.91 r0 bottom
L20 "2x90R" DLP11SN900HL2L 87.57,22.29 r0 bottom
L21 "2x90R" DLP11SN900HL2L 87.57,20.39 r0 bottom
L22 "2x90R/100MHz" USBSHOCK4-0805-12 54.02,34.83 r180 bottom
L23 "2x470uH / 1,6A" WE-SL5 6.2,37.46 r270 top
L24 "2.2uH/4A" LD-5X5M-VLC5045 13.55,54.06 r90 top
L25 "2.2uH/4A" LD-5X5M-VLC5045 13.52,46.54 r270 top
LED1 "LED Green" LED0603 1.78,11.89 r0 top
LED2 "LED Green" LED0603 1.78,10.1 r0 top
LED3 "LED Green" LED0603 1.78,8.38 r0 top
M1 "MM60-EZH059-B5-R650" MM60-EZH059-B5-R650 16.65,25.16 r270 bottom locked
Q1 "BSS138W" "SOT323 (SC70)" 10.84,24.5 r270 top
Q2 "BSS138W" "SOT323 (SC70)" 13.37,24.51 r270 top
Q3 "24MHz" XTALD-4-302X205M 41.021,43.434 r180 top
Q4 "BSS816" "SOT323 (SC70)" 85.91,9.39 r180 bottom
Q5 "BSS138W" "SOT323 (SC70)" 23.83,49.92 r180 top
Q6 "BSS138W" "SOT323 (SC70)" 34.15,56.06 r180 top
Q7 "BSS816" "SOT323 (SC70)" 39.83,8.92 r270 top
Q8 "BSS816" "SOT323 (SC70)" 39.83,13.29 r270 top
Q9 "BSS816" "SOT323 (SC70)" 85.9,11.85 r180 bottom
R1 "0R00" R0805 96.15,55.29 r270 bottom
R2 "0,01R" R0805 58.32,39.04 r270 bottom
R3 "10k" R0402 10.23,25.125 r270 bottom
R4 "10k" R0402 10.23,23.165 r90 bottom
R5 "4k7" R0402 86.1,14.35 r0 bottom
R6 "10k" R0402 8.21,28.43 r270 bottom
R7 "10k" R0402 4.4,27.73 r270 bottom
R8 "4k7" R0402 86.1,13.5 r0 bottom
R9 "4k7" R0402 86.1,15.2 r0 bottom
R10 "0R" R0402 34.81,49.16 r0 top
R11 "0R" R0402 43.4,50.8 r90 bottom
R12 "1M" R0402 40.894,46.482 r180 top
R13 "12k" R0402 43.8,47.67 r180 top
R14 "10k" R0402 42.75,55.41 r180 top
R15 "10k" R0402 34.8,52.7 r0 top
R16 "10k" R0402 34.8,50.95 r0 top
R17 "10k" R0402 34.8,50.05 r0 top
R18 "10k" R0402 35.76,46.65 r90 top
R19 "100k" R0402 78.96,31.9 r90 top
R20 "10K" R0402 81.03,31.9 r90 top
R21 "10k" R0402 78.56,29.51 r270 top
R22 "1k" R0402 54.26,42.21 r90 bottom
R23 "10K" R0402 85.82,47.08 r0 top
R24 "10K" R0402 83.24,47.08 r180 top
R25 "49R9" R0402 93.97,26.48 r0 top
R26 "47k" R0402 78.99,27.5 r270 top
R27 "49R9" R0402 79.33,36.63 r0 bottom
R28 "10K" R0402 78.19,30.56 r0 bottom
R29 "10K" R0402 82.5,35.84 r90 top
R30 "10k" R0402 31.14,61.49 r180 bottom
R31 "10k" R0402 31.15,65.62 r0 bottom
R32 "0R" R0402 29.6,60.94 r90 bottom
R33 "0R" R0402 38.94,24.16 r90 top
R34 "10k" R0402 42.09,28.46 r270 bottom
R35 "10k" R0402 43.005,28.46 r270 bottom
R36 "10k" R0402 43.01,18.46 r90 bottom
R37 "10k" R0402 42.12,18.46 r90 bottom
R38 "10k" R0402 40.08,18.45 r90 bottom
R39 "0R" R0402 39.815,21.514 r270 top
R40 "0R" R0402 38.925,19.486 r90 top
R41 "0R" R0402 39.815,19.486 r90 top
R42 "0R" R0402 38.925,21.514 r270 top
R43 "1k" R0402 6.83,10.36 r90 top
R44 "1k" R0402 9.37,10.36 r90 top
R45 "1k" R0402 11.91,10.36 r90 top
R46 "22k" R0402 77.93,41.36 r180 bottom
R47 "47k" R0402 77.93,40.26 r180 bottom
R48 "4k7" R0402 81.02,39.83 r180 bottom
R49 "100k" R0402 73.17,37.69 r270 bottom
R50 "4k7" R0402 89.06,10.61 r270 bottom
R51 "120R" R0402 11.23,10.92 r270 bottom
R52 "300R" R0402 85.61,47.99 r0 top
R53 "300R" R0402 74.797,47.99 r180 top
R54 "10k" R0402 42.96,31.59 r90 bottom
R55 "10k" R0402 74.02,25.56 r270 bottom
R56 "10k" R0402 74.02,23.64 r270 bottom
R57 "1k" R0402 1.51,11.9 r180 bottom
R58 "1k" R0402 1.5,10.1 r180 bottom
R59 "1k" R0402 1.51,8.38 r180 bottom
R60 "10k" R0402 22.71,51.71 r180 bottom
R62 "10k" R0402 30.04,49.48 r90 top
R63 "n.u." R0805 22.14,44.26 r0 bottom
R64 "150k" R0402 20.124,55.46 r180 top
R65 "100k" R0402 22.04,51.43 r90 top
R66 "100k" R0402 22.04,53.29 r270 top
R67 "16.5k" R0402 20.124,56.54 r0 top
R68 "10k" R0402 8.51,67.01 r270 top
R69 "0R" R0402 10.38,67.01 r270 top
R70 "0R" R0402 9.44,67.01 r270 top
R71 "47k" R0402 19.01,45.65 r180 top
R72 "75k" R0402 16.4,45.95 r270 bottom
R73 "100k" R0402 22.45,48.24 r180 top
R74 "n.u." R0402 18.31,49.89 r180 top
R75 "30k1" R0402 22.5,46.2 r180 top
R76 "0,01R" R0805 55.69,39.04 r90 bottom
R77 "24k" R0402 17.27,45.96 r90 bottom
R78 "10k" R0402 51.09,36.13 r0 bottom
R79 "1k" R0402 24.51,48.25 r180 top
R80 "150R" R0402 15.4,68.75 r270 bottom
R81 "221R" R0402 16.8,68.75 r270 bottom
R82 "150R" R0402 14,68.75 r270 bottom
R83 "10k" R0402 74.64,14.2 r270 bottom
R84 "150k" R0402 77.12,17.22 r0 bottom
R85 "75k" R0402 75.7,17.72 r270 bottom
R86 "10k" R0402 10.77,27.27 r270 top
R87 "150k" R0402 16.02,28.07 r90 top
R88 "56k" R0402 16.02,26.16 r90 top
R89 "23K2" R0402 31.17,56.635 r180 top
R90 "53k6" R0402 31.17,55.715 r180 top
R91 "1M" R0402 28.09,60.35 r270 top
R92 "10k" R0402 34.95,51.41 r0 bottom
R93 "10k" R0402 35.94,55.42 r270 bottom
R94 "10k" R0402 36.75,55.43 r270 bottom
R95 "0R" R0402 20.36,53.72 r270 bottom
R96 "10k" R0402 22.59,57.47 r90 bottom
R97 "0R" R0402 30.61,55.45 r180 bottom
R98 "10k" R0402 34.95,52.25 r0 bottom
R99 "4k7" R0402 39.83,11.03 r0 top
R100 "4k7" R0402 39.83,15.42 r0 top
R101 "4k7" R0402 88.14,10.61 r270 bottom
R102 "0R" R0402 36.84,51.7 r270 bottom
SP1 "Spacer M2" Spacer_M2 44.79,9.03 r0 top locked
SP2 "Spacer M2" Spacer_M2 76.223,44.454 r0 top locked
SW1 "2756" MCDM(R)-04-T 10.64,16.9 r0 top
T1 "BSS138W" "SOT323 (SC70)" 81.03,29.69 r0 top
T2 "SI2301BDS" SOT23-3 78.84,28.25 r180 bottom
T3 "BSS138W" "SOT323 (SC70)" 79.28,34.95 r180 bottom
T4 "BSS138W" "SOT323 (SC70)" 79.28,32.44 r180 bottom
T5 "SI2301BDS" SOT23-3 75.6,38.29 r180 bottom
T6 "BSS138W" "SOT323 (SC70)" 79.38,38.3 r180 bottom
T10 "EVQQ2201W" "EVQQ2 Switch" 11.9,3.5 r0 top
T11 "EVQQ2201W" "EVQQ2 Switch" 22.7,3.5 r0 top
T12 "436351045816" 436351045816 9.7,70.1 r180 top locked
TP1 "TESTPOINT" TESTPOINT 54.27,49.95 r0 top
TP2 "TESTPOINT" TESTPOINT 22.52,63.25 r90 top
TP3 "TESTPOINT" TESTPOINT 16.42,63.05 r90 top
TP4 "TESTPOINT" TESTPOINT 30.67,57.53 r90 top
TP5 "TESTPOINT" TESTPOINT 24.1,52.85 r90 top
TP6 "TESTPOINT" TESTPOINT 34.22,54.1 r90 top
TP7 "TESTPOINT" TESTPOINT 36.29,54.18 r90 top
TP8 "TESTPOINT" TESTPOINT 36.29,55.29 r90 top
TP9 "TESTPOINT" TESTPOINT 27.99,53.15 r90 top
TP10 "TESTPOINT" TESTPOINT 36.29,56.39 r90 top
TP11 "TESTPOINT" TESTPOINT 6.95,3.41 r270 bottom
TP12 "TESTPOINT" TESTPOINT 6.95,4.67 r270 bottom
TP13 "TESTPOINT" TESTPOINT 6.95,5.93 r270 bottom
TP14 "TESTPOINT" TESTPOINT 6.95,7.19 r270 bottom
TP15 "TESTPOINT" TESTPOINT 89.19,17.68 r90 top
TP16 "TESTPOINT" TESTPOINT 89.19,18.94 r90 top
TP17 "TESTPOINT" TESTPOINT 89.19,20.53 r90 top
TP18 "TESTPOINT" TESTPOINT 89.2,21.79 r90 top
TP19 "TESTPOINT" TESTPOINT 49.01,48.31 r0 top
TP20 "TESTPOINT" TESTPOINT 47.75,48.31 r0 top
TP21 "TESTPOINT" TESTPOINT 46.49,48.31 r0 top
TP22 "TESTPOINT" TESTPOINT 45.23,48.33 r0 top
TP23 "TESTPOINT" TESTPOINT 55.92,42.29 r0 bottom
TP24 "TESTPOINT" TESTPOINT 54.79,45.14 r0 bottom
TP25 "TESTPOINT" TESTPOINT 53.52,45.14 r0 bottom
TP26 "TESTPOINT" TESTPOINT 54.26,39.87 r0 bottom
TP27 "TESTPOINT" TESTPOINT 50.03,45.14 r0 bottom
TP28 "TESTPOINT" TESTPOINT 48.73,45.14 r0 bottom
TP29 "TESTPOINT" TESTPOINT 57.22,42.29 r90 bottom
TP30 "TESTPOINT" TESTPOINT 60.15,6.32 r90 top
TP31 "TESTPOINT" TESTPOINT 58.89,6.32 r90 top
U1 "MOUNT_HOLE" HOLE-3.2x6 3,3 r0 top
U2 "MOUNT_HOLE" HOLE-3.2x6 3,69 r0 top
U3 "MOUNT_HOLE" HOLE-3.2x6 97,3 r0 top
U4 "MOUNT_HOLE" HOLE-3.2x6 97,69 r0 top
U5 "MIC2026-1" MIC2026 28.67,47.61 r90 bottom
U6 "USB2514B" USB2514 40,51.39 r180 top
U7 "TVS Diode" SOT23-6 82.85,44.43 r90 top
U8 "TVS Diode" SOT23-6 86.23,44.41 r90 top
U9 "LDO 3.3V" SOT23-5 35.125,60.16 r90 bottom
U10 "SP3232ECY" TSSOP16-065M 38.33,35.88 r90 bottom
U11 "SP330E" TSSOP24_065P 39.42,23.42 r270 bottom
U12 "TVS Diode" SOT23-6 91.16,39.77 r180 bottom
U13 "TVS Diode" SOT23-6 91.16,35.4 r180 bottom
U14 "TVS Diode" SOT23-6 91.16,30.77 r180 bottom
U15 "TVS Diode" SOT23-6 91.16,25.5 r180 bottom
U16 "TVS Diode" SOT23-6 91.16,20.98 r180 bottom
U18 "TJA1051T/3" SOIC-8_M 6.87,10.93 r0 bottom
U20 "NCP303LSN30T1G" SOT23-5 27.54,50.94 r180 top
U21 "RT6150BGQW" SON50P250X80_HS-11N 19.11,53.24 r0 top
U22 "RT8070ZQW" WDFN8_0.65P_300X80 19.11,47.71 r180 top
U23 "ADP171" SOT23-5 76.68,14.66 r90 bottom
U24 "ADP171" SOT23-5 13.42,27.67 r0 top
U25 "PCMF3USB3S" WLCSP15 25.39,60.17 r270 top
U26 "CBTU02043" HUQFN16 22.59,57.46 r0 top
U27 "PCMF3USB3S" WLCSP15 20.202,60.137 r270 top
U28 "NX20P0407" WLCSP12 24.3,54.52 r180 top
U29 "NX5P3290" WLCSP16 28.34,58.07 r0 top
U30 "PTN5110" HX2QFN16 33.43,54.76 r0 bottom

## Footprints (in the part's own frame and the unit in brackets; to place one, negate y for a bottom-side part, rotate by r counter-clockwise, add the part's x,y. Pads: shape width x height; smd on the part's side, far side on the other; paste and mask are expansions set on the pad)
436351045816 [mm] "3.5x4.7 mm SMD J-Bend side push"
  rect 1.2x1 smd: 1(2.8,0.85) 2(2.8,-0.85) 3(-2.8,0.85) 4(-2.8,-0.85)
  round 0.75 hole 0.75 unplated: M1(0,1.375) M2(0,-1.375)
  silkscreen extent -2.35,-2.75 2.35,1.75, body extent -2.75,-2.75 2.75,1.75, height 1.67
691322310005 [mm] "Horizontal PCB Header, pitch 3.81mm, 05p"
  rect 2.1x2.1 hole 1.4: 1(-7.62,3.4)
  round 2.1 hole 1.4: 2(-3.81,3.4) 3(0,3.4) 4(3.81,3.4) 5(7.62,3.4)
  silkscreen extent -10.12,-4.6 10.12,4.6, body extent -10.12,-4.6 10.12,4.6, height 7.25
C0402 [mm]
  rect 0.66x0.62 smd: 1(-0.54,0) 2(0.54,0)
  body extent -0.53,-0.28 0.53,0.28, height 0.55
C0603 [mm] "Chip Capacitor, 2-Leads, Body 1,60x0,80mm, IPC Medium Density"
  rect 1x0.95 smd: 1(-0.75,0) 2(0.75,0)
  body extent -0.85,-0.45 0.85,0.45, height 0.9
C0805 [mm] "Chip Capacitor, 2-Leads, Body 1,55x0,80mm, IPC Low Density"
  rect 1x1.35 smd: 1(-0.9,0) 2(0.9,0)
  silkscreen extent -0.1,-0.58 0.1,0.58, body extent -1,-0.6 1,0.6, height 0.95
C1206 [mm] "Chip Capacitor, 2-Leads, Body 3,30x1,70mm, IPC Medium Density"
  rect 1.45x1.9 smd: 1(-1.575,0) 2(1.575,0)
  silkscreen extent -0.3,-0.85 0.3,0.85, body extent -1.8,-0.95 1.8,0.95, height 1.8
C_2312 [mm] "Molded Capacitor, 2-Leads, Body 6,00x3,25mm, IPC Medium Density"
  rect 2.7x2.3 smd: 1(-2.25,0) 2(2.25,0)
  silkscreen extent -3.87,-1.7 3.1,1.82, body extent -3.11,-1.68 2.99,1.68, height 2.67
COM-5X2 [mm]
  rect 1.7x1.7 hole 1 paste+0: 1(-5.08,-1.27)
  round 1.7 hole 1 paste+0: 2(-5.1,1.25) 3(-2.54,-1.27) 4(-2.56,1.25) 5(0,-1.27) 6(-0.02,1.25) 7(2.54,-1.27) 8(2.52,1.25) 9(5.08,-1.27) 10(5.06,1.25)
  body extent -10.18,-4.42 10.18,4.75, height 9.1
COM-25X2 [mm]
  rect 1.7x1.7 hole 1 paste+0: 1(-30.48,-1.27) 26(0,1.27)
  round 1.7 hole 1 paste+0: 2(-30.48,1.27) 3(-27.94,-1.27) 4(-27.94,1.27) 5(-25.4,-1.27) 6(-25.4,1.27) 7(-22.86,-1.27) 8(-22.86,1.27) 9(-20.32,-1.27) 10(-20.32,1.27) 11(-17.78,-1.27) 12(-17.78,1.27) 13(-15.24,-1.27) 14(-15.24,1.27) 15(-12.7,-1.27) 16(-12.7,1.27) 17(-10.16,-1.27) 18(-10.16,1.27) 19(-7.62,-1.27) 20(-7.62,1.27) 21(-5.08,-1.27) 22(-5.08,1.27) 23(-2.54,-1.27) 24(-2.54,1.27) 25(0,-1.27) 27(2.54,-1.27) 28(2.54,1.27) 29(5.08,-1.27) 30(5.08,1.27) 31(7.62,-1.27) 32(7.62,1.27) 33(10.16,-1.27) 34(10.16,1.27) 35(12.7,-1.27) 36(12.7,1.27) 37(15.24,-1.27) 38(15.24,1.27) 39(17.78,-1.27) 40(17.78,1.27) 41(20.32,-1.27) 42(20.32,1.27) 43(22.86,-1.27) 44(22.86,1.27) 45(25.4,-1.27) 46(25.4,1.27) 47(27.94,-1.27) 48(27.94,1.27) 49(30.48,-1.27) 50(30.48,1.27)
  body extent -31.75,-2.54 31.75,2.54, height 9.49
DF13-4P-1.25H(20) [mm]
  rect 0.7x1.8 smd paste+0.05: 1(-1.875,-3.5) 2(-0.625,-3.5) 3(0.625,-3.5) 4(1.875,-3.5)
  rect 1.6x2.4 smd paste+0.1: 9(4.225,-0.2) 10(-4.225,-0.2)
  body extent -4.83,-4 4.82,2.5, height 3.6
DF13-6P-1.25H(20) [mm]
  rect 0.7x1.8 smd paste+0.05: 1(-3.125,-3.5) 2(-1.875,-3.5) 3(-0.625,-3.5) 4(0.625,-3.5) 5(1.875,-3.5) 6(3.125,-3.5)
  rect 1.6x2.4 smd paste+0.1: 9(5.475,-0.2) 10(-5.475,-0.2)
  body extent -6.08,-4 6.07,2.5, height 3.6
DF40C-30DS-0.4V(51) [mm]
  rect 1.131x0.2 smd paste-5 mask+0: 1(-1.375,-2.8) 2(1.375,-2.8) 3(-1.375,-2.4) 4(1.375,-2.4) 5(-1.375,-2) 6(1.375,-2) 7(-1.375,-1.6) 8(1.375,-1.6) 9(-1.375,-1.2) 10(1.375,-1.2) 11(-1.375,-0.8) 12(1.375,-0.8) 13(-1.375,-0.4) 14(1.375,-0.4) 15(-1.375,0) 16(1.375,0) 17(-1.375,0.4) 18(1.375,0.4) 19(-1.375,0.8) 20(1.375,0.8) 21(-1.375,1.2) 22(1.375,1.2) 23(-1.375,1.6) 24(1.375,1.6) 25(-1.375,2) 26(1.375,2) 27(-1.375,2.4) 28(1.375,2.4) 29(-1.375,2.8) 30(1.375,2.8)
  body extent -1.69,-4.3 1.69,4.3, height 1.45
DF40C-100DS-0.4V(51) [mm]
  rect 0.2x0.7 smd paste+0 mask+0: 1(-9.8,-1.59) 2(-9.8,1.59) 3(-9.4,-1.59) 4(-9.4,1.59) 5(-9,-1.59) 6(-9,1.59) 7(-8.6,-1.59) 8(-8.6,1.59) 9(-8.2,-1.59) 10(-8.2,1.59) 11(-7.8,-1.59) 12(-7.8,1.59) 13(-7.4,-1.59) 14(-7.4,1.59) 15(-7,-1.59) 16(-7,1.59) 17(-6.6,-1.59) 18(-6.6,1.59) 19(-6.2,-1.59) 20(-6.2,1.59) 21(-5.8,-1.59) 22(-5.8,1.59) 23(-5.4,-1.59) 24(-5.4,1.59) 25(-5,-1.59) 26(-5,1.59) 27(-4.6,-1.59) 28(-4.6,1.59) 29(-4.2,-1.59) 30(-4.2,1.59) 31(-3.8,-1.59) 32(-3.8,1.59) 33(-3.4,-1.59) 34(-3.4,1.59) 35(-3,-1.59) 36(-3,1.59) 37(-2.6,-1.59) 38(-2.6,1.59) 39(-2.2,-1.59) 40(-2.2,1.59) 41(-1.8,-1.59) 42(-1.8,1.59) 43(-1.4,-1.59) 44(-1.4,1.59) 45(-1,-1.59) 46(-1,1.59) 47(-0.6,-1.59) 48(-0.6,1.59) 49(-0.2,-1.59) 50(-0.2,1.59) 51(0.2,-1.59) 52(0.2,1.59) 53(0.6,-1.59) 54(0.6,1.59) 55(1,-1.59) 56(1,1.59) 57(1.4,-1.59) 58(1.4,1.59) 59(1.8,-1.59) 60(1.8,1.59) 61(2.2,-1.59) 62(2.2,1.59) 63(2.6,-1.59) 64(2.6,1.59) 65(3,-1.59) 66(3,1.59) 67(3.4,-1.59) 68(3.4,1.59) 69(3.8,-1.59) 70(3.8,1.59) 71(4.2,-1.59) 72(4.2,1.59) 73(4.6,-1.59) 74(4.6,1.59) 75(5,-1.59) 76(5,1.59) 77(5.4,-1.59) 78(5.4,1.59) 79(5.8,-1.59) 80(5.8,1.59) 81(6.2,-1.59) 82(6.2,1.59) 83(6.6,-1.59) 84(6.6,1.59) 85(7,-1.59) 86(7,1.59) 87(7.4,-1.59) 88(7.4,1.59) 89(7.8,-1.59) 90(7.8,1.59) 91(8.2,-1.59) 92(8.2,1.59) 93(8.6,-1.59) 94(8.6,1.59) 95(9,-1.59) 96(9,1.59) 97(9.4,-1.59) 98(9.4,1.59) 99(9.8,-1.59) 100(9.8,1.59)
  Top Layer region: -9.9,-1.257 -9.7,-1.257 -9.7,-0.8 -9.9,-0.8
  Top Layer region: 9.7,0.809 9.9,0.809 9.9,1.249 9.7,1.249
  Top Layer region: 9.3,0.809 9.5,0.809 9.5,1.249 9.3,1.249
  Top Layer region: 8.9,0.809 9.1,0.809 9.1,1.249 8.9,1.249
  Top Layer region: 8.5,0.809 8.7,0.809 8.7,1.249 8.5,1.249
  Top Layer region: 8.1,0.809 8.3,0.809 8.3,1.249 8.1,1.249
  Top Layer region: 7.7,0.809 7.9,0.809 7.9,1.249 7.7,1.249
  Top Layer region: 7.3,0.809 7.5,0.809 7.5,1.249 7.3,1.249
  Top Layer region: 6.9,0.809 7.1,0.809 7.1,1.249 6.9,1.249
  Top Layer region: 6.5,0.809 6.7,0.809 6.7,1.249 6.5,1.249
  Top Layer region: 6.1,0.809 6.3,0.809 6.3,1.249 6.1,1.249
  Top Layer region: 5.7,0.809 5.9,0.809 5.9,1.249 5.7,1.249
  Top Layer region: 5.3,0.809 5.5,0.809 5.5,1.249 5.3,1.249
  Top Layer region: 4.9,0.809 5.1,0.809 5.1,1.249 4.9,1.249
  Top Layer region: 4.5,0.809 4.7,0.809 4.7,1.249 4.5,1.249
  Top Layer region: 4.1,0.809 4.3,0.809 4.3,1.249 4.1,1.249
  Top Layer region: 3.7,0.809 3.9,0.809 3.9,1.249 3.7,1.249
  Top Layer region: 3.3,0.809 3.5,0.809 3.5,1.249 3.3,1.249
  Top Layer region: 2.9,0.809 3.1,0.809 3.1,1.249 2.9,1.249
  Top Layer region: 2.5,0.809 2.7,0.809 2.7,1.249 2.5,1.249
  Top Layer region: 2.1,0.809 2.3,0.809 2.3,1.249 2.1,1.249
  Top Layer region: 1.7,0.809 1.9,0.809 1.9,1.249 1.7,1.249
  Top Layer region: 1.3,0.809 1.5,0.809 1.5,1.249 1.3,1.249
  Top Layer region: 0.9,0.809 1.1,0.809 1.1,1.249 0.9,1.249
  Top Layer region: 0.5,0.809 0.7,0.809 0.7,1.249 0.5,1.249
  Top Layer region: 0.1,0.809 0.3,0.809 0.3,1.249 0.1,1.249
  Top Layer region: -0.3,0.809 -0.1,0.809 -0.1,1.249 -0.3,1.249
  Top Layer region: -0.7,0.809 -0.5,0.809 -0.5,1.249 -0.7,1.249
  Top Layer region: -1.1,0.809 -0.9,0.809 -0.9,1.249 -1.1,1.249
  Top Layer region: -1.5,0.809 -1.3,0.809 -1.3,1.249 -1.5,1.249
  Top Layer region: -1.9,0.809 -1.7,0.809 -1.7,1.249 -1.9,1.249
  Top Layer region: -2.3,0.809 -2.1,0.809 -2.1,1.249 -2.3,1.249
  Top Layer region: -2.7,0.809 -2.5,0.809 -2.5,1.249 -2.7,1.249
  Top Layer region: -3.1,0.809 -2.9,0.809 -2.9,1.249 -3.1,1.249
  Top Layer region: -3.5,0.809 -3.3,0.809 -3.3,1.249 -3.5,1.249
  Top Layer region: -3.9,0.809 -3.7,0.809 -3.7,1.249 -3.9,1.249
  Top Layer region: -4.3,0.809 -4.1,0.809 -4.1,1.249 -4.3,1.249
  Top Layer region: -4.7,0.809 -4.5,0.809 -4.5,1.249 -4.7,1.249
  Top Layer region: -5.1,0.809 -4.9,0.809 -4.9,1.249 -5.1,1.249
  Top Layer region: -5.5,0.809 -5.3,0.809 -5.3,1.249 -5.5,1.249
  Top Layer region: -5.9,0.809 -5.7,0.809 -5.7,1.249 -5.9,1.249
  Top Layer region: -6.3,0.809 -6.1,0.809 -6.1,1.249 -6.3,1.249
  Top Layer region: -6.7,0.809 -6.5,0.809 -6.5,1.249 -6.7,1.249
  Top Layer region: -7.1,0.809 -6.9,0.809 -6.9,1.249 -7.1,1.249
  Top Layer region: -7.5,0.809 -7.3,0.809 -7.3,1.249 -7.5,1.249
  Top Layer region: -7.9,0.809 -7.7,0.809 -7.7,1.249 -7.9,1.249
  Top Layer region: -8.3,0.809 -8.1,0.809 -8.1,1.249 -8.3,1.249
  Top Layer region: -8.7,0.809 -8.5,0.809 -8.5,1.249 -8.7,1.249
  Top Layer region: -9.1,0.809 -8.9,0.809 -8.9,1.249 -9.1,1.249
  Top Layer region: -9.5,0.809 -9.3,0.809 -9.3,1.249 -9.5,1.249
  Top Layer region: -9.9,0.809 -9.7,0.809 -9.7,1.249 -9.9,1.249
  Top Layer region: 8.1,-1.257 8.3,-1.257 8.3,-0.8 8.1,-0.8
  Top Layer region: -8.3,-1.257 -8.1,-1.257 -8.1,-0.8 -8.3,-0.8
  Top Layer region: 9.7,-1.257 9.9,-1.257 9.9,-0.8 9.7,-0.8
  Top Layer region: 9.3,-1.257 9.5,-1.257 9.5,-0.8 9.3,-0.8
  Top Layer region: 8.9,-1.257 9.1,-1.257 9.1,-0.8 8.9,-0.8
  Top Layer region: 8.5,-1.257 8.7,-1.257 8.7,-0.8 8.5,-0.8
  Top Layer region: 7.7,-1.257 7.9,-1.257 7.9,-0.8 7.7,-0.8
  Top Layer region: 7.3,-1.257 7.5,-1.257 7.5,-0.8 7.3,-0.8
  Top Layer region: 6.9,-1.257 7.1,-1.257 7.1,-0.8 6.9,-0.8
  Top Layer region: 6.5,-1.257 6.7,-1.257 6.7,-0.8 6.5,-0.8
  Top Layer region: 6.1,-1.257 6.3,-1.257 6.3,-0.8 6.1,-0.8
  Top Layer region: 5.7,-1.257 5.9,-1.257 5.9,-0.8 5.7,-0.8
  Top Layer region: 5.3,-1.257 5.5,-1.257 5.5,-0.8 5.3,-0.8
  Top Layer region: 4.9,-1.257 5.1,-1.257 5.1,-0.8 4.9,-0.8
  Top Layer region: 4.5,-1.257 4.7,-1.257 4.7,-0.8 4.5,-0.8
  Top Layer region: 4.1,-1.257 4.3,-1.257 4.3,-0.8 4.1,-0.8
  Top Layer region: 3.7,-1.257 3.9,-1.257 3.9,-0.8 3.7,-0.8
  Top Layer region: 3.3,-1.257 3.5,-1.257 3.5,-0.8 3.3,-0.8
  Top Layer region: 2.9,-1.257 3.1,-1.257 3.1,-0.8 2.9,-0.8
  Top Layer region: 2.5,-1.257 2.7,-1.257 2.7,-0.8 2.5,-0.8
  Top Layer region: 2.1,-1.257 2.3,-1.257 2.3,-0.8 2.1,-0.8
  Top Layer region: 1.7,-1.257 1.9,-1.257 1.9,-0.8 1.7,-0.8
  Top Layer region: 1.3,-1.257 1.5,-1.257 1.5,-0.8 1.3,-0.8
  Top Layer region: 0.9,-1.257 1.1,-1.257 1.1,-0.8 0.9,-0.8
  Top Layer region: 0.5,-1.257 0.7,-1.257 0.7,-0.8 0.5,-0.8
  Top Layer region: 0.1,-1.257 0.3,-1.257 0.3,-0.8 0.1,-0.8
  Top Layer region: -0.3,-1.257 -0.1,-1.257 -0.1,-0.8 -0.3,-0.8
  Top Layer region: -0.7,-1.257 -0.5,-1.257 -0.5,-0.8 -0.7,-0.8
  Top Layer region: -1.1,-1.257 -0.9,-1.257 -0.9,-0.8 -1.1,-0.8
  Top Layer region: -1.5,-1.257 -1.3,-1.257 -1.3,-0.8 -1.5,-0.8
  Top Layer region: -1.9,-1.257 -1.7,-1.257 -1.7,-0.8 -1.9,-0.8
  Top Layer region: -2.3,-1.257 -2.1,-1.257 -2.1,-0.8 -2.3,-0.8
  Top Layer region: -2.7,-1.257 -2.5,-1.257 -2.5,-0.8 -2.7,-0.8
  Top Layer region: -3.1,-1.257 -2.9,-1.257 -2.9,-0.8 -3.1,-0.8
  Top Layer region: -3.5,-1.257 -3.3,-1.257 -3.3,-0.8 -3.5,-0.8
  Top Layer region: -3.9,-1.257 -3.7,-1.257 -3.7,-0.8 -3.9,-0.8
  Top Layer region: -4.3,-1.257 -4.1,-1.257 -4.1,-0.8 -4.3,-0.8
  Top Layer region: -4.7,-1.257 -4.5,-1.257 -4.5,-0.8 -4.7,-0.8
  Top Layer region: -5.1,-1.257 -4.9,-1.257 -4.9,-0.8 -5.1,-0.8
  Top Layer region: -5.5,-1.257 -5.3,-1.257 -5.3,-0.8 -5.5,-0.8
  Top Layer region: -5.9,-1.257 -5.7,-1.257 -5.7,-0.8 -5.9,-0.8
  Top Layer region: -6.3,-1.257 -6.1,-1.257 -6.1,-0.8 -6.3,-0.8
  Top Layer region: -6.7,-1.257 -6.5,-1.257 -6.5,-0.8 -6.7,-0.8
  Top Layer region: -7.1,-1.257 -6.9,-1.257 -6.9,-0.8 -7.1,-0.8
  Top Layer region: -7.5,-1.257 -7.3,-1.257 -7.3,-0.8 -7.5,-0.8
  Top Layer region: -7.9,-1.257 -7.7,-1.257 -7.7,-0.8 -7.9,-0.8
  Top Layer region: -8.7,-1.257 -8.5,-1.257 -8.5,-0.8 -8.7,-0.8
  Top Layer region: -9.1,-1.257 -8.9,-1.257 -8.9,-0.8 -9.1,-0.8
  Top Layer region: -9.5,-1.257 -9.3,-1.257 -9.3,-0.8 -9.5,-0.8
  body extent -11.3,-1.69 11.3,1.69, height 1.45
DLP11SN900HL2L [mm] "Chip Common Mode Choke Coil"
  rect 0.8x0.3 smd mask+0: 1(-0.675,0.275) 2(0.675,0.275) 3(0.675,-0.275) 4(-0.675,-0.275)
  body extent -0.62,-0.5 0.63,0.5, height 0.92
DO-214AB [mm] "Molded Diode, 2-Leads, Body 6,88x5,90mm, IPC Medium Density"
  rect 2.4x3.15 smd: 1(-2.85,0) 2(2.85,0)
  silkscreen extent -4.38,-3.15 3.6,3.15, body extent -3.79,-3.13 3.79,3.13, height 2.65
"EVQQ2 Switch" [mm]
  rect 3.2x1 smd paste+0: 1(-3.4,2) 2(3.4,2) 3(-3.4,-2) 4(3.4,-2)
  body extent -3.3,-3 3.3,3, height 2.01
